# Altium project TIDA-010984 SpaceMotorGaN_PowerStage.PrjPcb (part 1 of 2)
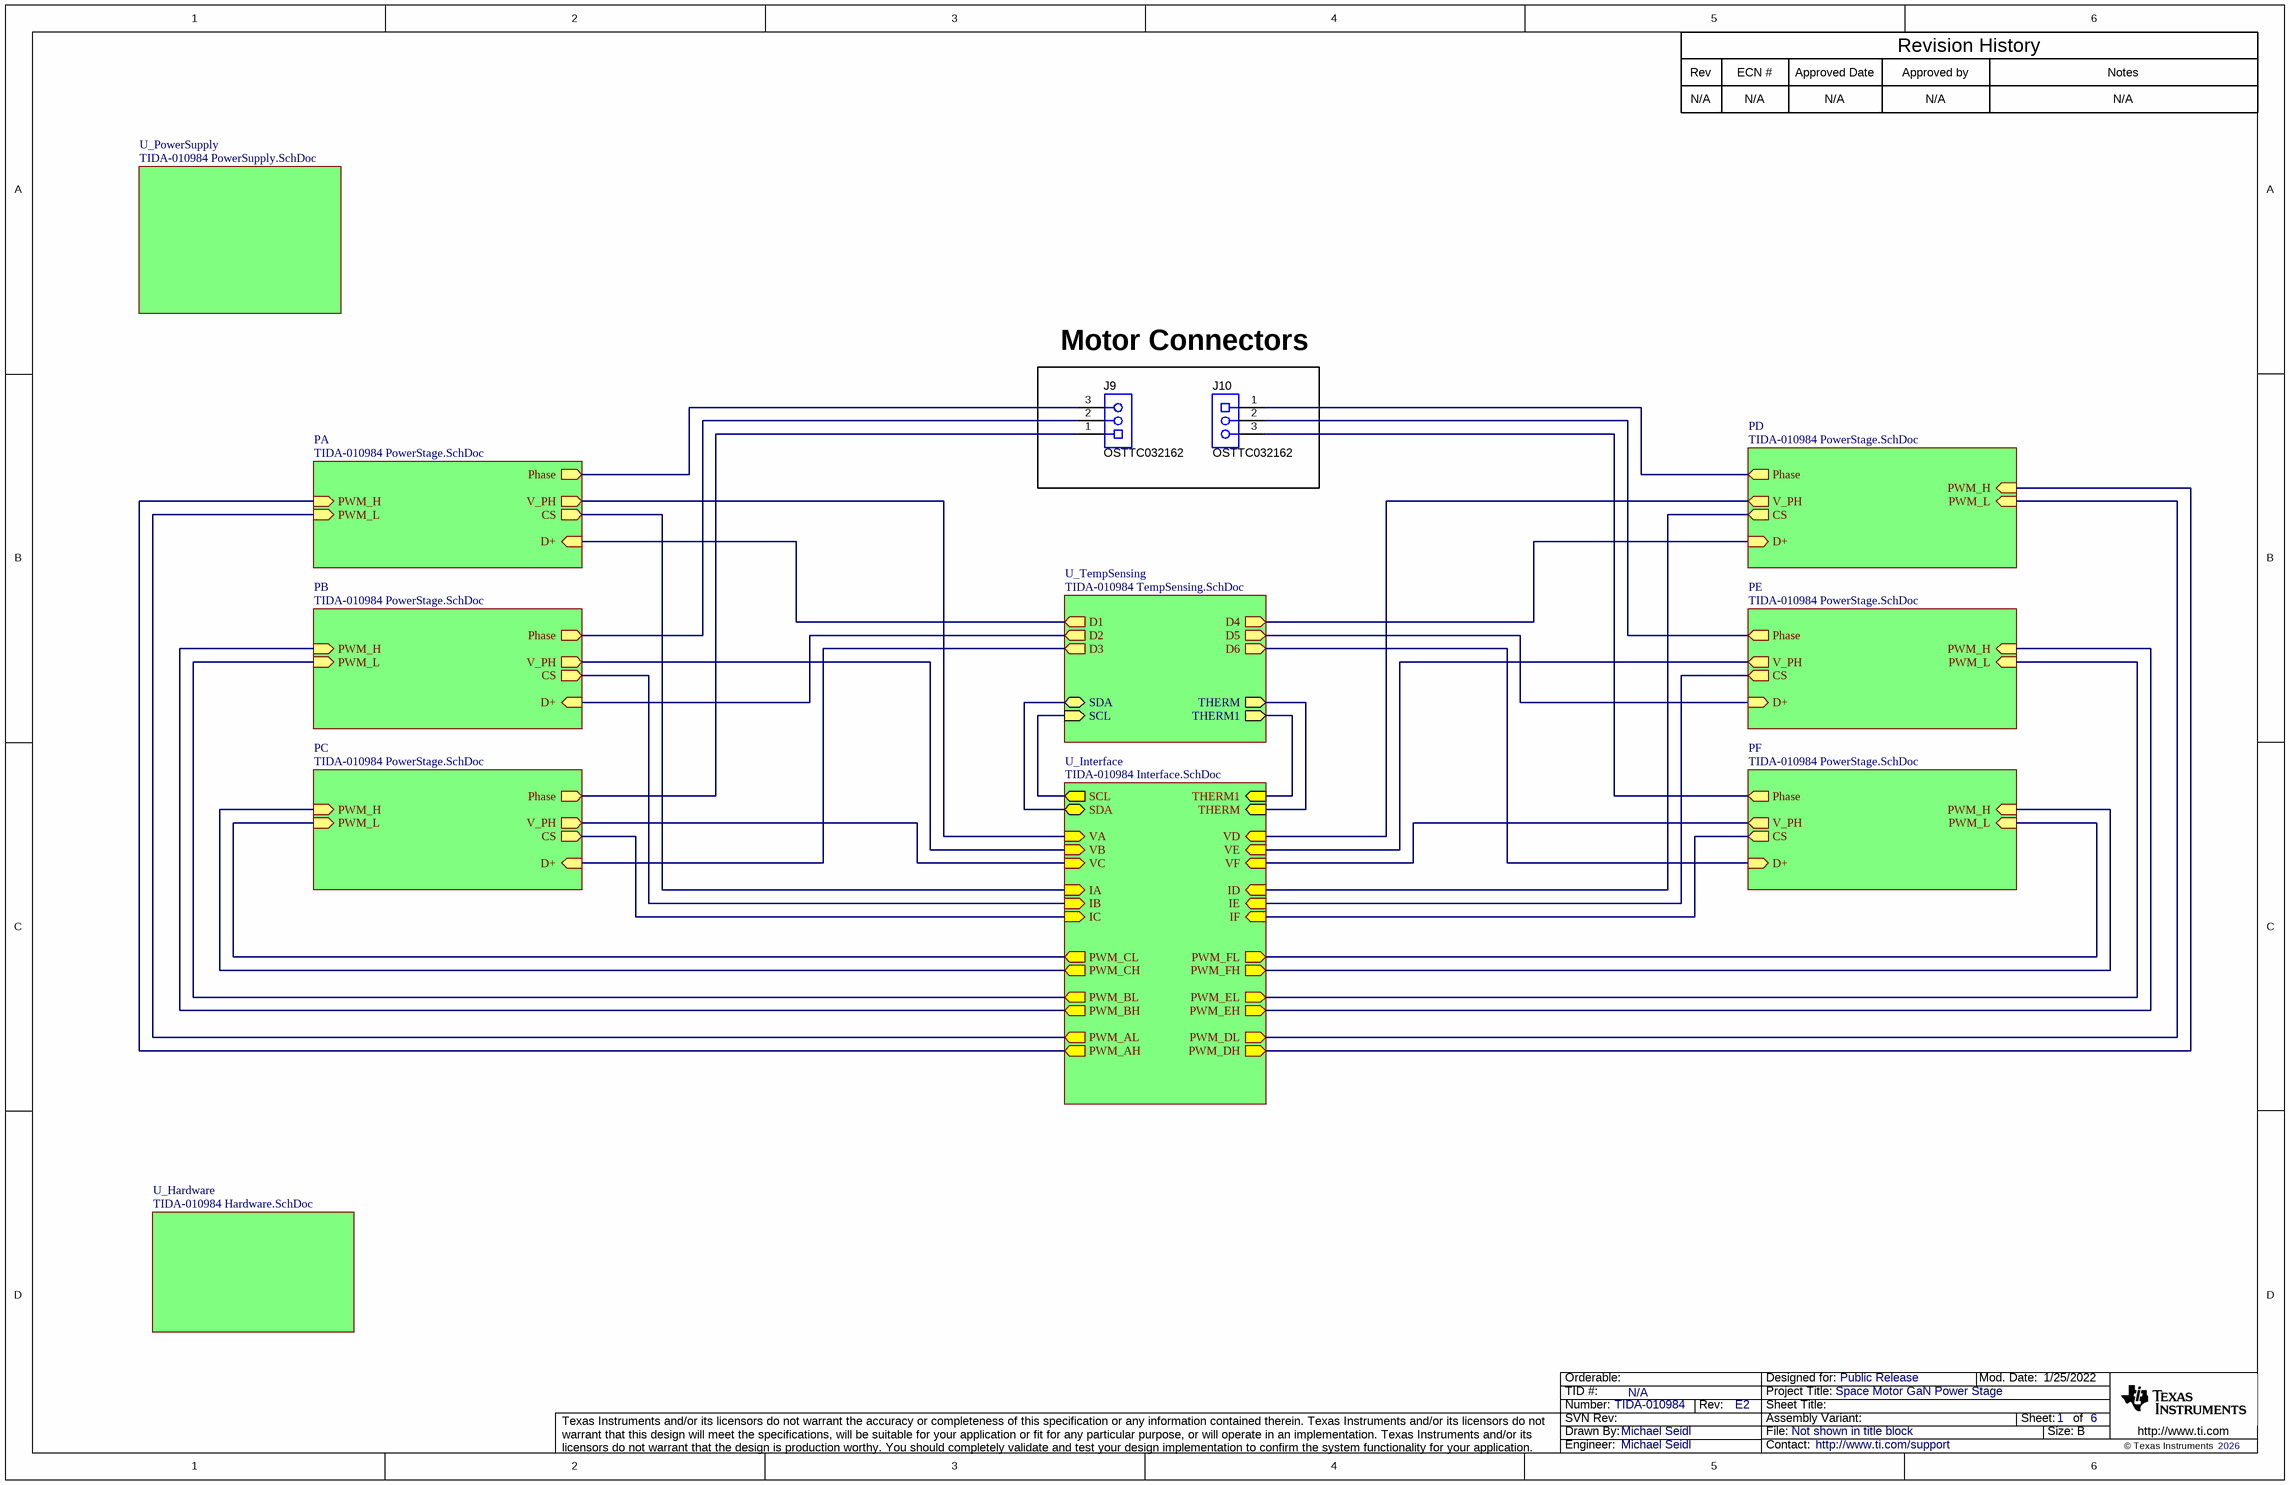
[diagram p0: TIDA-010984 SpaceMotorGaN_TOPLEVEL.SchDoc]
CopyrightYear: 2026; PCB_Layout: Michael Seidl; PCB_Rev: E2; PRJ_Customer: Public Release; PRJ_Engineer: Michael Seidl; PRJ_Number: TIDA-010984; PRJ_Title: Space Motor GaN Power Stage; SCH_Rev: E2; TechSupport: http://www.ti.com/support; TID: N/A
6 sheets, 583 parts. Net scope: hierarchical (ports join the sheet entries above them; power ports are global).
Board file: TIDA-010984 SpaceMotorGaN_PowerStage.PcbDoc
Sheets:
  TIDA-010984 SpaceMotorGaN_TOPLEVEL.SchDoc
    PA = TIDA-010984 PowerStage.SchDoc
    PB = TIDA-010984 PowerStage.SchDoc
    PC = TIDA-010984 PowerStage.SchDoc
    PE = TIDA-010984 PowerStage.SchDoc
    PD = TIDA-010984 PowerStage.SchDoc
    PF = TIDA-010984 PowerStage.SchDoc
    U_Interface = TIDA-010984 Interface.SchDoc
    U_Hardware = TIDA-010984 Hardware.SchDoc
    U_TempSensing = TIDA-010984 TempSensing.SchDoc
    U_PowerSupply = TIDA-010984 PowerSupply.SchDoc

## Sheet TIDA-010984 SpaceMotorGaN_TOPLEVEL.SchDoc
size 431 x 279 mm; Date: Not shown in title block; ApprovedBy: Not shown in title block; CheckedBy: Not shown in title block; Author: Not shown in title block; CompanyName: Not shown in title block; DrawnBy: Michael Seidl; Engineer: Not shown in title block; Organization: Not shown in title block; Address1: Not shown in title block; Address2: Not shown in title block; Address3: Not shown in title block; Address4: Not shown in title block; DocumentNumber: 1; Revision: Use project parameter SCH_Rev; SheetNumber: 1; SheetTotal: 6; PageSetup: Record=PageOptions¦CenterHorizontal=True¦CenterVertical=True¦PrintScale=1.00¦XCorrection=1.00¦YCorrection=1.00¦PrintKind=0¦BorderSize=5000000¦LeftOffset=0¦BottomOffset=0¦Orientation=2¦PaperLength=1000¦PaperWidth=1000¦Scale=100¦PaperSource=15¦PrintQuality=600¦MediaType=1¦DitherType=10¦PaperKind=Letter¦PrintScaleMode=1

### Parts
J9  OSTTC032162  [On-Shore_OSTTC032162]
J10  OSTTC032162  [On-Shore_OSTTC032162]

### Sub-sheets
PA = TIDA-010984 PowerStage.SchDoc: Phase (out), V_PH (out), PWM_H (in), PWM_L (in), CS (out), D+ (in)
PB = TIDA-010984 PowerStage.SchDoc: Phase (out), V_PH (out), PWM_H (in), PWM_L (in), CS (out), D+ (in)
PC = TIDA-010984 PowerStage.SchDoc: Phase (out), V_PH (out), PWM_H (in), PWM_L (in), CS (out), D+ (in)
PD = TIDA-010984 PowerStage.SchDoc: Phase (out), V_PH (out), CS (out), PWM_H (in), PWM_L (in), D+ (in)
PE = TIDA-010984 PowerStage.SchDoc: Phase (out), V_PH (out), CS (out), PWM_H (in), PWM_L (in), D+ (in)
PF = TIDA-010984 PowerStage.SchDoc: Phase (out), V_PH (out), CS (out), PWM_H (in), PWM_L (in), D+ (in)
U_Hardware = TIDA-010984 Hardware.SchDoc: no entries
U_Interface = TIDA-010984 Interface.SchDoc: SDA (bidir), SCL (out), THERM (in), THERM1 (in), PWM_AH (out), PWM_AL (out), PWM_BH (out), PWM_BL (out), PWM_CH (out), PWM_CL (out), PWM_DH (out), PWM_DL (out), PWM_EH (out), PWM_EL (out), PWM_FH (out), PWM_FL (out), VA (in), VB (in), VC (in), IA (in), IB (in), IC (in), VD (in), VE (in), VF (in), ID (in), IE (in), IF (in)
U_PowerSupply = TIDA-010984 PowerSupply.SchDoc: no entries
U_TempSensing = TIDA-010984 TempSensing.SchDoc: THERM (out), THERM1 (out), SDA (bidir), SCL (in), D1 (out), D2 (out), D3 (out), D4 (out), D5 (out), D6 (out)

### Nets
CS: sheet PA/CS, sheet U_Interface/IA
CS: sheet PB/CS, sheet U_Interface/IB  [a separate net that carries the same name]
CS: sheet PC/CS, sheet U_Interface/IC  [a separate net that carries the same name]
CS: sheet PE/CS, sheet U_Interface/IE  [a separate net that carries the same name]
CS: sheet PD/CS, sheet U_Interface/ID  [a separate net that carries the same name]
CS: sheet PF/CS, sheet U_Interface/IF  [a separate net that carries the same name]
D+: sheet PA/D+, sheet U_TempSensing/D1
D+: sheet PB/D+, sheet U_TempSensing/D2  [a separate net that carries the same name]
D+: sheet PC/D+, sheet U_TempSensing/D3  [a separate net that carries the same name]
D+: sheet PE/D+, sheet U_TempSensing/D5  [a separate net that carries the same name]
D+: sheet PD/D+, sheet U_TempSensing/D4  [a separate net that carries the same name]
D+: sheet PF/D+, sheet U_TempSensing/D6  [a separate net that carries the same name]
Phase: J10.1 ; sheet PD/Phase
Phase: J10.2 ; sheet PE/Phase  [a separate net that carries the same name]
Phase: J10.3 ; sheet PF/Phase  [a separate net that carries the same name]
Phase: J9.1 ; sheet PC/Phase  [a separate net that carries the same name]
Phase: J9.2 ; sheet PB/Phase  [a separate net that carries the same name]
Phase: J9.3 ; sheet PA/Phase  [a separate net that carries the same name]
PWM_AH: sheet PA/PWM_H, sheet U_Interface/PWM_AH
PWM_AL: sheet PA/PWM_L, sheet U_Interface/PWM_AL
PWM_BH: sheet PB/PWM_H, sheet U_Interface/PWM_BH
PWM_BL: sheet PB/PWM_L, sheet U_Interface/PWM_BL
PWM_CH: sheet PC/PWM_H, sheet U_Interface/PWM_CH
PWM_CL: sheet PC/PWM_L, sheet U_Interface/PWM_CL
PWM_DH: sheet PD/PWM_H, sheet U_Interface/PWM_DH
PWM_DL: sheet PD/PWM_L, sheet U_Interface/PWM_DL
PWM_EH: sheet PE/PWM_H, sheet U_Interface/PWM_EH
PWM_EL: sheet PE/PWM_L, sheet U_Interface/PWM_EL
PWM_FH: sheet PF/PWM_H, sheet U_Interface/PWM_FH
PWM_FL: sheet PF/PWM_L, sheet U_Interface/PWM_FL
SCL: sheet U_Interface/SCL, sheet U_TempSensing/SCL
SDA: sheet U_Interface/SDA, sheet U_TempSensing/SDA
THERM: sheet U_Interface/THERM, sheet U_TempSensing/THERM
THERM1: sheet U_Interface/THERM1, sheet U_TempSensing/THERM1
V_PH: sheet PA/V_PH, sheet U_Interface/VA
V_PH: sheet PB/V_PH, sheet U_Interface/VB  [a separate net that carries the same name]
V_PH: sheet PC/V_PH, sheet U_Interface/VC  [a separate net that carries the same name]
V_PH: sheet PE/V_PH, sheet U_Interface/VE  [a separate net that carries the same name]
V_PH: sheet PD/V_PH, sheet U_Interface/VD  [a separate net that carries the same name]
V_PH: sheet PF/V_PH, sheet U_Interface/VF  [a separate net that carries the same name]

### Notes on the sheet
- Rev
- N/A
- ECN #
- Approved Date
- Approved by
- Revision History
- Notes
- Motor Connectors

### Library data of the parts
J9 J10 = CMP-0075292-1: Terminal Block, 3x1, 5.08 mm, Tin, TH; Manufacturer: On-Shore Technology; Pitch_mm: 5.08; Gender: Female; Row_Count: 1; Current_A: 15A; Voltage_V: 300V; Cert_UL: Y; CNHeader: False; CT: True

## Sheet TIDA-010984 PowerStage.SchDoc
size 431 x 279 mm; Date: Not shown in title block; ApprovedBy: Not shown in title block; CheckedBy: Not shown in title block; Author: Not shown in title block; CompanyName: Not shown in title block; DrawnBy: Michael Seidl; Engineer: Not shown in title block; Organization: Not shown in title block; Address1: Not shown in title block; Address2: Not shown in title block; Address3: Not shown in title block; Address4: Not shown in title block; DocumentNumber: 2; Revision: Use project parameter SCH_Rev; SheetNumber: 4; SheetTotal: 6; PageSetup: Record=PageOptions¦CenterHorizontal=True¦CenterVertical=True¦PrintScale=1.00¦XCorrection=1.00¦YCorrection=1.00¦PrintKind=0¦BorderSize=5000000¦LeftOffset=0¦BottomOffset=0¦Orientation=2¦PaperLength=1000¦PaperWidth=1000¦Scale=100¦PaperSource=15¦PrintQuality=600¦MediaType=1¦DitherType=10¦PaperKind=Letter¦PrintScaleMode=1
Used 6 times, as channels PA, PB, PC, PE, PD, PF. Parts and nets are listed once, with the designators drawn on the sheet.
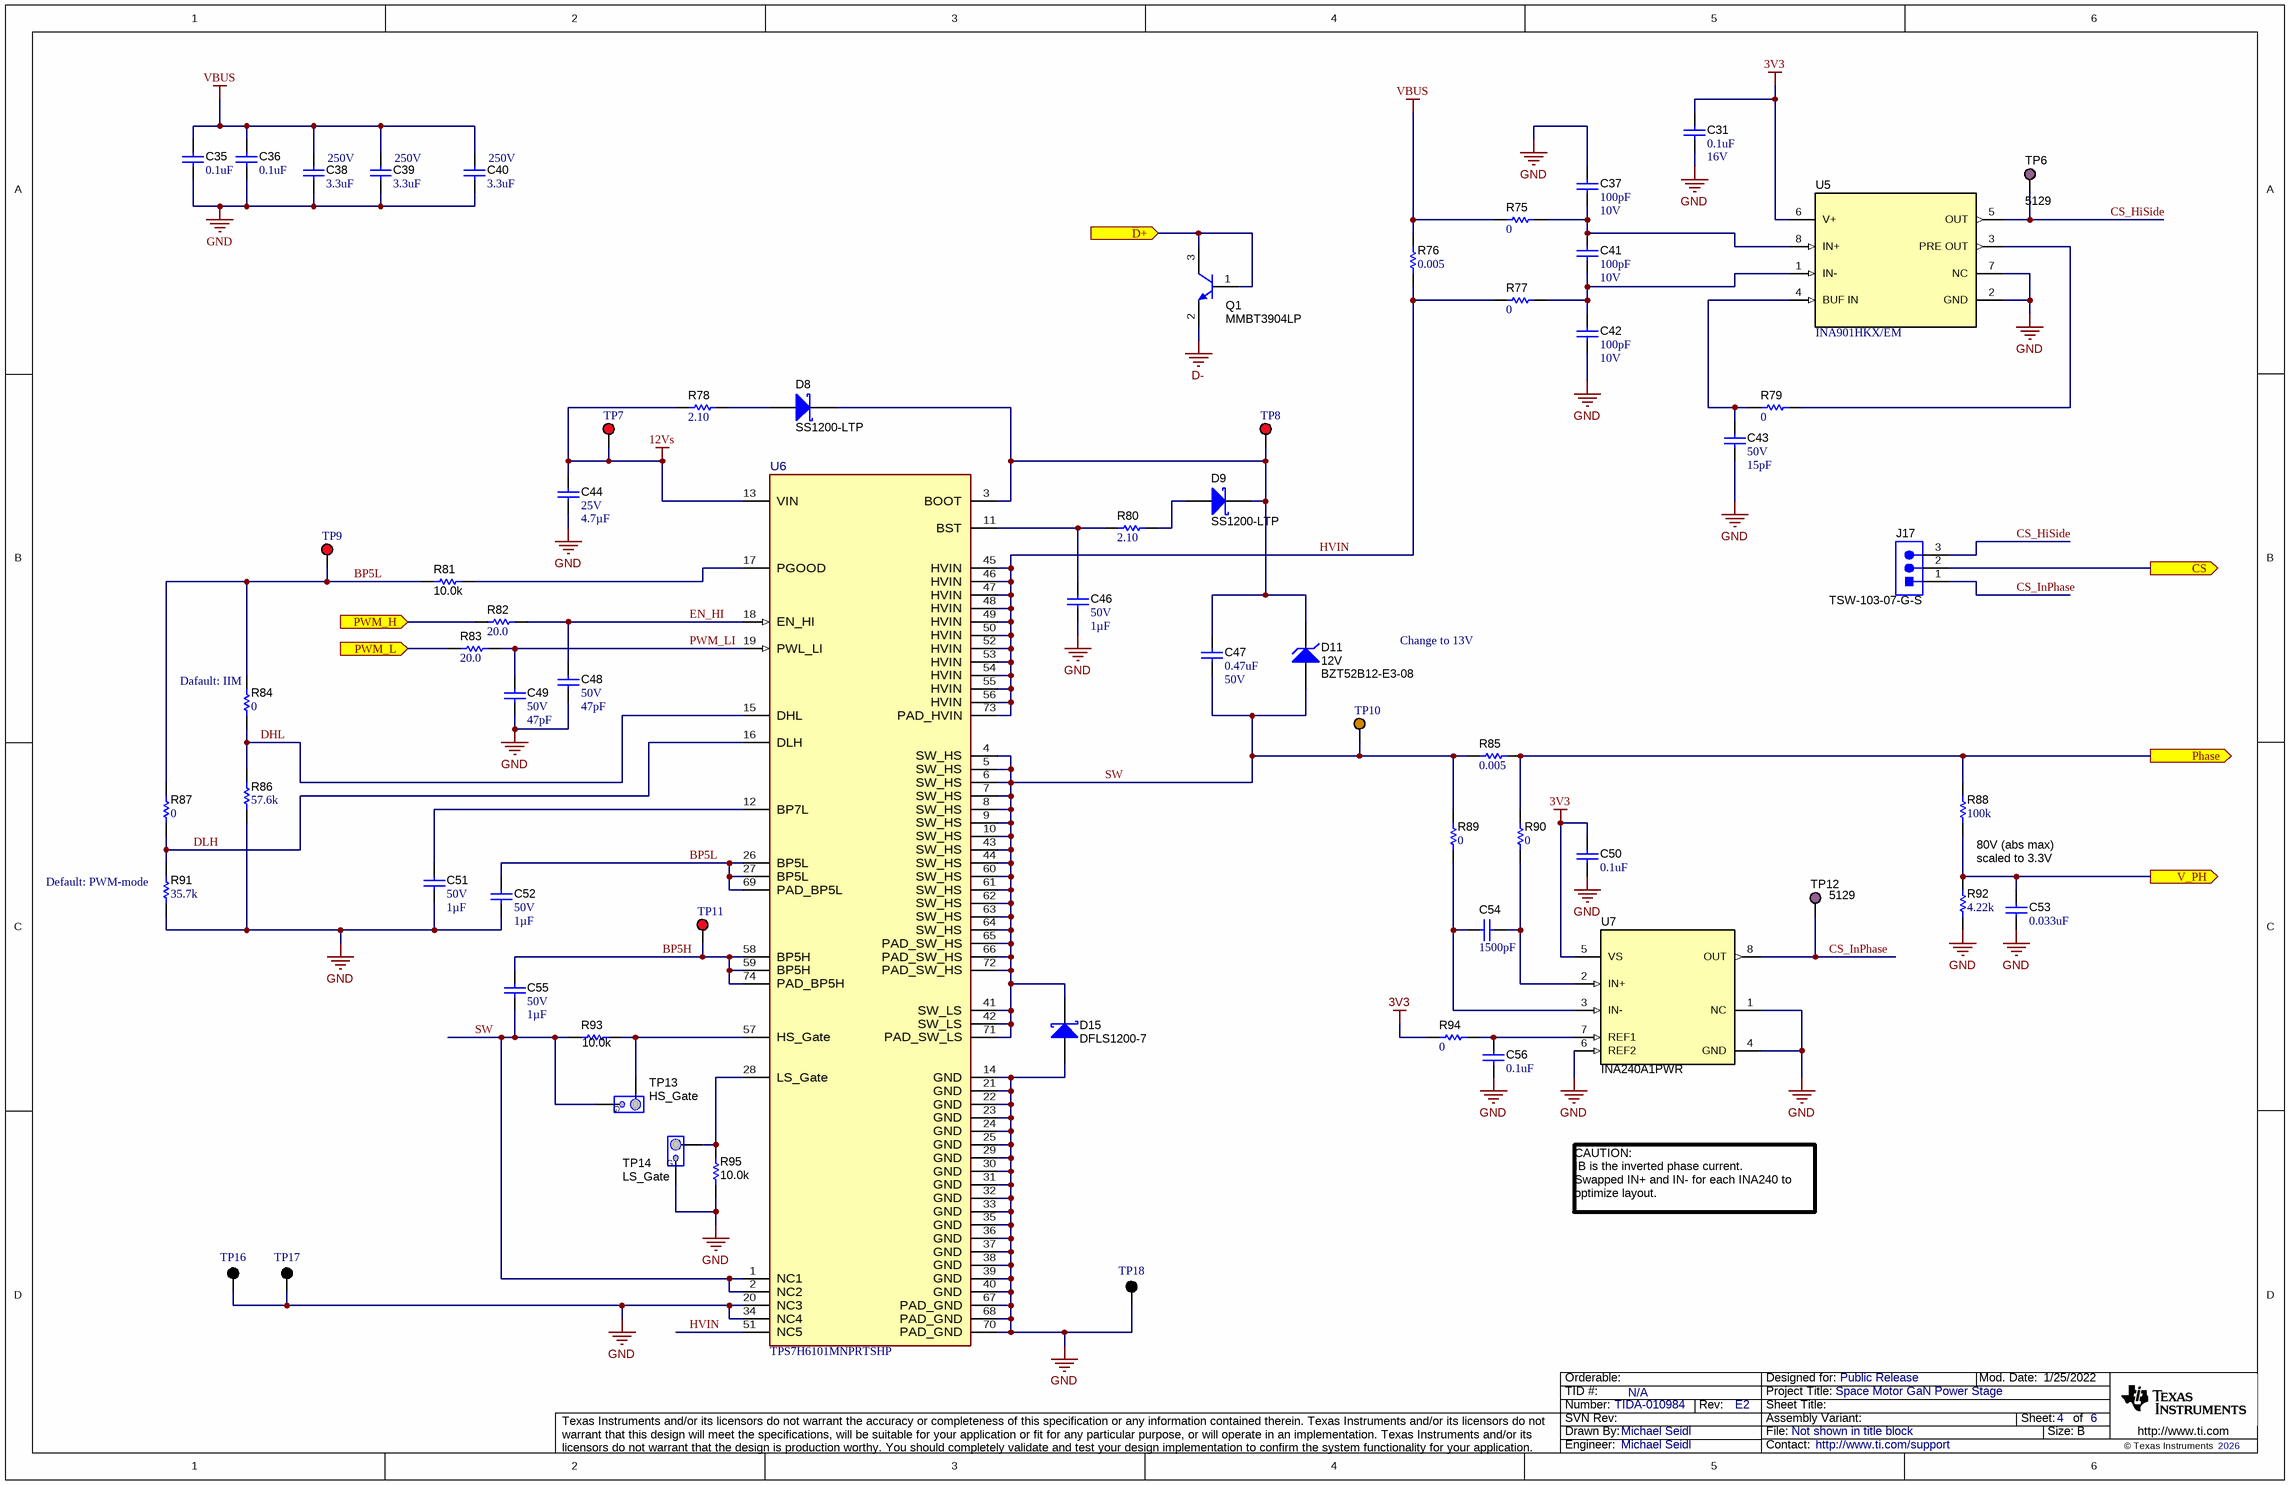
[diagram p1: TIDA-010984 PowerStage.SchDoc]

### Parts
C31  ValueDisplayed: 0.1uF  VDC_V: 16V  [0603]  (hidden comment: GRM188R71C104KA01D)
C35  ValueDisplayed: 0.1uF  [1206_180]  (hidden comment: GRM31CR72E104KW03L)
C36  ValueDisplayed: 0.1uF  [1206_180]  (hidden comment: GRM31CR72E104KW03L)
C37  Cap_F: 100pF  VDC_V: 10V  [0603]  (hidden comment: 0603ZC101KAT2A)
C38  ValueDisplayed: 3.3uF  Value2: 250V  [CKG57N]  (hidden comment: CKG57NX7T2E335M500JH)
C39  ValueDisplayed: 3.3uF  Value2: 250V  [CKG57N]  (hidden comment: CKG57NX7T2E335M500JH)
C40  ValueDisplayed: 3.3uF  Value2: 250V  [CKG57N]  (hidden comment: CKG57NX7T2E335M500JH)
C41  Cap_F: 100pF  VDC_V: 10V  [0603]  (hidden comment: 0603ZC101KAT2A)
C42  Cap_F: 100pF  VDC_V: 10V  [0603]  (hidden comment: 0603ZC101KAT2A)
C43  VDC_V: 50V  ValueDisplayed: 15pF  [0603]  (hidden comment: GCM1885C1H150JA16D)
C44  VDC_V: 25V  ValueDisplayed: 4.7µF  [0805L]  (hidden comment: CGA4J1X7R1E475K125AC)
C46  VDC_V: 50V  ValueDisplayed: 1µF  [0805_HV]  (hidden comment: 08055C105K4Z2A)
C47  ValueDisplayed: 0.47uF  VDC_V: 50V  [0603]  (hidden comment: CGA3E3X7R1H474K080AE)
C48  VDC_V: 50V  ValueDisplayed: 47pF  [0603]  (hidden comment: CGA3E2NP01H470J080AA)
C49  VDC_V: 50V  ValueDisplayed: 47pF  [0603]  (hidden comment: CGA3E2NP01H470J080AA)
C50  ValueDisplayed: 0.1uF  [0603]  (hidden comment: GRM188R71C104KA01D)
C51  VDC_V: 50V  ValueDisplayed: 1µF  [0805_HV]  (hidden comment: 08055C105K4Z2A)
C52  VDC_V: 50V  ValueDisplayed: 1µF  [0805_HV]  (hidden comment: 08055C105K4Z2A)
C53  ValueDisplayed: 0.033uF  [0603]  (hidden comment: GRM188R71C333KA01D)
C54  ValueDisplayed: 1500pF  [0603]  (hidden comment: GRM1885C1E152JA01D)
C55  VDC_V: 50V  ValueDisplayed: 1µF  [0805_HV]  (hidden comment: 08055C105K4Z2A)
C56  ValueDisplayed: 0.1uF  [0603]  (hidden comment: GRM188R71C104KA01D)
D8  SS1200-LTP  [SMA]
D9  SS1200-LTP  [SMA]
D11  BZT52B12-E3-08  value 12V  [SOD-123]
D15  DFLS1200-7  [PowerDI123]
J17  TSW-103-07-G-S  [TSW-103-07-G-S]
Q1  MMBT3904LP  [DIODES_X1-DFN1006-3]
R75  ValueDisplayed: 0  [0603]  (hidden comment: RC0603JR-070RL)
R76  ValueDisplayed: 0.005  [CRE2512-R5_R9]  (hidden comment: CRE2512-FZ-R005E-3)
R77  ValueDisplayed: 0  [0603]  (hidden comment: RC0603JR-070RL)
R78  ValueDisplayed: 2.10  [0603]  (hidden comment: RC0603FR-072R1L)
R79  ValueDisplayed: 0  [0603]  (hidden comment: RC0603JR-070RL)
R80  ValueDisplayed: 2.10  [0603]  (hidden comment: RC0603FR-072R1L)
R81  ValueDisplayed: 10.0k  [0603]  (hidden comment: RC0603FR-0710KL)
R82  ValueDisplayed: 20.0  [0603]  (hidden comment: CRCW060320R0FKEA)
R83  ValueDisplayed: 20.0  [0603]  (hidden comment: CRCW060320R0FKEA)
R84  ValueDisplayed: 0  [0603]  (hidden comment: RC0603JR-070RL)
R85  ValueDisplayed: 0.005  [CRE2512-R5_R9]  (hidden comment: CRE2512-FZ-R005E-3)
R86  ValueDisplayed: 57.6k  [0603]  (hidden comment: RC0603FR-0757K6L)
R87  ValueDisplayed: 0  [0603]  (hidden comment: RC0603JR-070RL)
R88  ValueDisplayed: 100k  [0603]  (hidden comment: RC0603FR-07100KL)
R89  ValueDisplayed: 0  [0603]  (hidden comment: RC0603JR-070RL)
R90  ValueDisplayed: 0  [0603]  (hidden comment: RC0603JR-070RL)
R91  ValueDisplayed: 35.7k  [0603]  (hidden comment: RC0603FR-0735K7L)
R92  ValueDisplayed: 4.22k  [0603]  (hidden comment: RC0603FR-074K22L)
R93  ValueDisplayed: 10.0k  [0603]  (hidden comment: RC0603FR-0710KL)
R94  ValueDisplayed: 0  [0603]  (hidden comment: RC0603JR-070RL)
R95  ValueDisplayed: 10.0k  [0603]  (hidden comment: RC0603FR-0710KL)
TP6  5129  [Keystone5129]
TP7  5010  [Keystone5010]  (value not drawn)
TP8  5010  [Keystone5010]  (value not drawn)
TP9  5010  [Keystone5010]  (value not drawn)
TP10  5013  [Keystone5013]  (value not drawn)
TP11  5010  [Keystone5010]  (value not drawn)
TP12  5129  [Keystone5129]
TP13  HS_Gate  [TESTPOINT_PIGTAIL]  (no BOM)
TP14  LS_Gate  [TESTPOINT_PIGTAIL]  (no BOM)
TP16  5011  [Keystone5011]  (value not drawn)
TP17  5011  [Keystone5011]  (value not drawn)
TP18  5011  [Keystone5011]  (value not drawn)
U5  INA901HKX/EM  [HKX0008A_Custom_A]
U6  TPS7H6101MNPRTSHP  [NPR0064A-MFG]
U7  INA240A1PWR  [PW0008A_L]

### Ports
CS (out), D+ (in), Phase (out), PWM_H (in), PWM_L (in), V_PH (out)

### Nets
3V3: C31.1 C50.2 R94.1 U5.6(V+) U7.5(VS)
12Vs: C44.2 R78.2 TP7.1 U6.13(VIN)
D-: Q1.2(E)
GND: C31.2 C35.2 C36.2 C37.1 C38.2 C39.2 C40.2 C42.2 C43.2 C44.1 C46.1 C48.2 C49.2 C50.1 C51.1 C52.1 C53.2 C56.1 D15.2(A) R86.2 R91.2 R92.1 R95.1 TP14.2 TP16.1 TP17.1 TP18.1 U5.2(GND) U5.7(NC) U6.14(GND) U6.20(NC3) U6.21(GND) U6.22(GND) U6.23(GND) U6.24(GND) U6.25(GND) U6.29(GND) U6.30(GND) U6.31(GND) U6.32(GND) U6.33(GND) U6.34(NC4) U6.35(GND) U6.36(GND) U6.37(GND) U6.38(GND) U6.39(GND) U6.40(GND) U6.67(PAD_GND) U6.68(PAD_GND) U6.70(PAD_GND) U7.1(NC) U7.4(GND) U7.6(REF2)
VBUS: C35.1 C36.1 C38.1 C39.1 C40.1 R75.1 R76.2
BP5H: C55.2 TP11.1 U6.58(BP5H) U6.59(BP5H) U6.74(PAD_BP5H)
BP5L: C52.2 R81.2 R84.1 R87.1 TP9.1 U6.26(BP5L) U6.27(BP5L) U6.69(PAD_BP5L)
CS: J17.2 ; port CS
CS_HiSide: J17.3 TP6.1 U5.5(OUT)
CS_InPhase: J17.1 TP12.1 U7.8(OUT)
D+: Q1.1(B) Q1.3(C) ; port D+
DHL: R84.2 R86.1 U6.15(DHL)
DLH: R87.2 R91.1 U6.16(DLH)
EN_HI: C48.1 R82.1 U6.18(EN_HI)
HVIN: R76.1 R77.1 U6.45(HVIN) U6.46(HVIN) U6.47(HVIN) U6.48(HVIN) U6.49(HVIN) U6.50(HVIN) U6.51(NC5) U6.52(HVIN) U6.53(HVIN) U6.54(HVIN) U6.55(HVIN) U6.56(HVIN) U6.73(PAD_HVIN)
Phase: R85.2 R88.2 R90.1 ; port Phase
PWM_H: R82.2 ; port PWM_H
PWM_L: R83.2 ; port PWM_L
PWM_LI: C49.1 R83.1 U6.19(PWL_LI)
SW: C47.2 C55.1 D11.2(A) D15.1(K) R85.1 R89.1 R93.2 TP10.1 TP13.2 U6.1(NC1) U6.2(NC2) U6.4(SW_HS) U6.5(SW_HS) U6.6(SW_HS) U6.7(SW_HS) U6.8(SW_HS) U6.9(SW_HS) U6.10(SW_HS) U6.41(SW_LS) U6.42(SW_LS) U6.43(SW_HS) U6.44(SW_HS) U6.60(SW_HS) U6.61(SW_HS) U6.62(SW_HS) U6.63(SW_HS) U6.64(SW_HS) U6.65(PAD_SW_HS) U6.66(PAD_SW_HS) U6.71(PAD_SW_LS) U6.72(PAD_SW_HS)
V_PH: C53.1 R88.1 R92.2 ; port V_PH
NetC37_2: C37.2 C41.1 R75.2 U5.8(IN+)
NetC41_2: C41.2 C42.1 R77.2 U5.1(IN-)
NetC43_1: C43.1 R79.1 U5.4(BUF_IN)
NetC46_2: C46.2 R80.2 U6.11(BST)
NetC47_1: C47.1 D8.1(K) D9.1(K) D11.1(K) TP8.1 U6.3(BOOT)
NetC51_2: C51.2 U6.12(BP7L)
NetC54_1: C54.1 R89.2 U7.3(IN-)
NetC54_2: C54.2 R90.2 U7.2(IN+)
NetC56_2: C56.2 R94.2 U7.7(REF1)
NetD8_2: D8.2(A) R78.1
NetD9_2: D9.2(A) R80.1
NetR79_2: R79.2 U5.3(PRE_OUT)
NetR81_1: R81.1 U6.17(PGOOD)
NetR93_1: R93.1 TP13.1 U6.57(HS_Gate)
NetR95_2: R95.2 TP14.1 U6.28(LS_Gate)

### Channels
PA: designators end in _PA; ports CS=CS D+=D+ Phase=Phase PWM_H=PWM_AH PWM_L=PWM_AL V_PH=V_PH
PB: designators end in _PB; ports CS=CS D+=D+ Phase=Phase PWM_H=PWM_BH PWM_L=PWM_BL V_PH=V_PH
PC: designators end in _PC; ports CS=CS D+=D+ Phase=Phase PWM_H=PWM_CH PWM_L=PWM_CL V_PH=V_PH
PE: designators end in _PE; ports CS=CS D+=D+ Phase=Phase PWM_H=PWM_EH PWM_L=PWM_EL V_PH=V_PH
PD: designators end in _PD; ports CS=CS D+=D+ Phase=Phase PWM_H=PWM_DH PWM_L=PWM_DL V_PH=V_PH
PF: designators end in _PF; ports CS=CS D+=D+ Phase=Phase PWM_H=PWM_FH PWM_L=PWM_FL V_PH=V_PH

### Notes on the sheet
- (near R84) Dafault: IIM
- Change to 13V
- (near R91) Default: PWM-mode
- 80V (abs max) scaled to 3.3V
- CAUTION:
  IB is the inverted phase current.
  Swapped IN+ and IN- for each INA240 to optimize layout.

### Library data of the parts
C31 = CMP-0007378-5: CAP, CERM, 0.1 uF, 16 V, +/- 10%, X7R, 0603; Manufacturer: MuRata; SizeArea_mm2: 1.28; SizeX_mm: 1.6; U/M: EA; Value: 0.1uF; TaMin_C: -55°C; Polarized: N; SizeZ_mm: 1; Value1: Unknown; SizeY_mm: 0.8; Cap_F: 100nF; TaMax_C: 125°C; SizeAreaWB_mm2: 4.68; AEC Category: Q200
C35 C36 = CMP-0008973-2: CAP, CERM, 0.1 uF, 250 V, +/- 10%, X7R, 1206; Manufacturer: MuRata; TaMin_C: -55°C; Polarized: N; SizeAreaWB_mm2: 10.92; Value1: Unknown; U/M: EA; Value: 0.1uF; TaMax_C: 125°C; SizeZ_mm: 1.8; SizeX_mm: 3.2; SizeY_mm: 1.6; Cap_Case: 1206; Value2: 250V; SizeArea_mm2: 5.12; CompType: Capacitor; Cap_F: 100nF; AEC Category: Q200
C37 C41 C42 = CMP-0006812-4: CAP, CERM, 100 pF, 10 V, +/- 10%, X7R, 0603; Manufacturer: AVX; TaMin_C: -55°C; Polarized: N; SizeAreaWB_mm2: 4.68; Value1: Unknown; U/M: EA; Value: 100pF; TaMax_C: 125°C; SizeZ_mm: 1; SizeX_mm: 1.6; SizeY_mm: 0.8; SizeArea_mm2: 1.28; AEC Category: Q200
C38-C40 = CMP-0009427-2: CAP, CERM, 3.3 uF, 250 V, +/- 20%, X7T, AEC-Q200 Grade 1, 6x5x5mm; Manufacturer: TDK; Polarized: N; Value: 3.3uF; U/M: EA; Cap_F: 3.3µF; Value1: Unknown; TaMin_C: -55°C; TaMax_C: 125°C; Cap_Case: 2220; AEC Category: Q200; AEC Qualified: Y; AEC Grade: 1; SizeAreaWB_mm2: 56; SizeZ_mm: 5.5; SizeX_mm: 6; SizeY_mm: 5; SizeArea_mm2: 30
C43 = CMP-0007126-4: CAP, CERM, 15 pF, 50 V, +/- 5%, C0G/NP0, AEC-Q200 Grade 1, 0603; Manufacturer: MuRata; TaMin_C: -55°C; Polarized: N; SizeAreaWB_mm2: 4.68; Value1: Unknown; U/M: EA; Value: 15pF; TaMax_C: 125°C; SizeZ_mm: 1; SizeX_mm: 1.6; SizeY_mm: 0.8; SizeArea_mm2: 1.28; AEC Qualified: Y; AEC Category: Q200
C44 = CMP-0076706-1: CAP, CERM, 4.7 µF, 25 V,+/- 10%, X7R, AEC-Q200 Grade 1, 0805; Manufacturer: TDK; TaMin_C: -55°C; Polarized: N; SizeAreaWB_mm2: 6.75; U/M: EA; Value: 4.7uF; TaMax_C: 125°C; SizeZ_mm: 1.45; SizeX_mm: 2.0; SizeY_mm: 1.25; Cap_Case: 2x1.25x1.25mm; SizeArea_mm2: 2.5; AEC Qualified: Y; AEC Grade: 1; AEC Category: Q200
C46 C51 C52 C55 = CMP-0083705-1: CAP, CERM, 1 µF, 50 V,+/- 10%, X7R, AEC-Q200 Grade 1, 0805; Manufacturer: AVX; TaMin_C: -55°C; Polarized: N; SizeAreaWB_mm2: 6.75; U/M: EA; Value: 1uF; TaMax_C: 125°C; SizeZ_mm: 1.45; SizeX_mm: 2; SizeY_mm: 1.25; Cap_Case: 0805; SizeArea_mm2: 2.5; AEC Qualified: Y; AEC Grade: 1; AEC Category: Q200
C47 = CMP-0007097-4: CAP, CERM, 0.47 uF, 50 V, +/- 10%, X7R, AEC-Q200 Grade 1, 0603; Manufacturer: TDK; SizeArea_mm2: 1.28; AEC Qualified: Y; SizeX_mm: 1.6; U/M: EA; Value: 0.47uF; TaMin_C: -55°C; Polarized: N; AEC Grade: 1; Value1: Unknown; SizeY_mm: 0.8; Cap_F: 470nF; TaMax_C: 125°C; SizeAreaWB_mm2: 4.68; AEC Category: Q200
C48 C49 = CMP-0080062-1: CAP, CERM, 47 pF, 50 V,+/- 5%, C0G/NP0, AEC-Q200 Grade 0, 0603; Manufacturer: TDK; TaMin_C: -55°C; Polarized: N; SizeAreaWB_mm2: 4.68; U/M: EA; Value: 47pF; TaMax_C: 150°C; SizeZ_mm: 1; SizeX_mm: 1.6; SizeY_mm: 0.8; SizeArea_mm2: 1.28; AEC Qualified: Y; AEC Grade: 0; AEC Category: Q200
C50 C56 = CMP-0007378-5: CAP, CERM, 0.1 uF, 16 V, +/- 10%, X7R, 0603; Manufacturer: MuRata; Polarized: N; Value: 0.1uF; U/M: EA; Cap_F: 100nF; Value1: Unknown; VDC_V: 16V; TaMin_C: -55°C; TaMax_C: 125°C; AEC Category: Q200; SizeArea_mm2: 1.28; SizeAreaWB_mm2: 4.68; SizeX_mm: 1.6; SizeY_mm: 0.8; SizeZ_mm: 1
C53 = CMP-0007392-5: CAP, CERM, 0.033 uF, 16 V, +/- 10%, X7R, 0603; Manufacturer: MuRata; Polarized: N; U/M: EA; Cap_F: 33nF; Value1: Unknown; VDC_V: 16V; TaMin_C: -55°C; TaMax_C: 125°C; AEC Category: Q200; SizeArea_mm2: 1.28; SizeAreaWB_mm2: 4.68; SizeX_mm: 1.6; SizeY_mm: 0.8; SizeZ_mm: 1
C54 = CMP-0007163-4: CAP, CERM, 1500 pF, 25 V, +/- 5%, C0G/NP0, 0603; Manufacturer: MuRata; TaMin_C: -55°C; Polarized: N; SizeAreaWB_mm2: 4.68; Value1: Unknown; U/M: EA; Value: 1500pF; TaMax_C: 125°C; SizeZ_mm: 1; SizeX_mm: 1.6; SizeY_mm: 0.8; Value2: 25V; SizeArea_mm2: 1.28; Cap_F: 1.5nF; AEC Category: Q200
D8 D9 = CMP-0028981-2: Diode, Schottky, 200 V, 1 A, SMA; Manufacturer: Micro Commercial Components; TJmax_C: 150°C; SizeArea_mm2: 16.3228; Io_A: 1A; AEC Qualified: N; SizeX_mm: 5.59; SizeZ_mm: 2.87; Vf_V: 920mV; Value: 200V; AEC Category: Q101; Value2: 0.92V; SizeY_mm: 2.92; SizeAreaWB_mm2: 37.3428
D11 = CMP-0005773-4: Diode, Zener, 12 V, 500 mW, AEC-Q101, SOD-123; Manufacturer: Vishay-Semiconductor; SizeX_mm: 3.85; RJA_CperW: 300; SizeY_mm: 1.7; AEC Qualified: Y; SizeZ_mm: 1.35; Power_W: 500mW; AEC Category: Q101; SizeAreaWB_mm2: 13.095; Value1: 0.5W; SizeArea_mm2: 6.545
D15 = CMP-0028517-2: Diode, Schottky, 200 V, 1 A, PowerDI123; Manufacturer: Diodes Inc.; Vr_V: 200V; SizeZ_mm: 0.98; Value: 200V; TJmax_C: 175°C; SizeY_mm: 1.78; Vf_V: 850mV; Green_REACh: Passed; Io_A: 1A; Value2: 0.85V; SizeAreaWB_mm2: 13.066; SizeArea_mm2: 6.586; Green_Lifecycle: Active; AEC Category: Q101; SizeX_mm: 3.7; RJC_CperW: 7
J17 = CMP-0075407-2: Header, 100mil, 3x1, Gold, TH; Manufacturer: Samtec; Pitch_mm: 2.54; Cert_VDE: N; Gender: Male; Cert_CSA: Y; Voltage_V: 550V; Green_REACh: Passed; Current_A: 6.3A; Green_Lifecycle: Active; Row_Count: 1
Q1 = CMP-0000409-2: Transistor, NPN, 40 V, 0.2 A, 3-UFDFN; Manufacturer: Diodes Inc.; CompType: BJT; PNP: 0; NPN: 1; Vceo_V: 40V; Vcesat1_V: 300mV; Value: 40 V; IcRated_A: 200mA; Value1: 0.2 A; HfeMax: 400; TaMin_C: -55°C; TaMax_C: 150°C; U/M: EA; AEC Category: Q101; SizeY_mm: 0.6; SizeZ_mm: 0.53; SizeAreaWB_mm2: 3.2
R75 R77 R79 R84 R87 R89 R90 R94 = CMP-0025885-5: RES, 0, 5%, 0.1 W, 0603; Manufacturer: Yageo; Power_W: 100mW; TempCo: 200 ppm/C; Value_Code: 0000; Value: 0; EIA_Code: E24; SizeX_mm: 1.6; SizeY_mm: 0.8; SizeZ_mm: 1; Value2: 0.1W; SizeArea_mm2: 1.28; AEC Qualified: N; VDC_V: 75V; AEC Category: Q200; SizeAreaWB_mm2: 4.68
R76 R85 = CMP-0015751-2: RES, 0.005, 1%, 3 W, AEC-Q200 Grade 0, 2512; Manufacturer: Bourns; Value: 0.005; Res_ohm: 5m; Value_Code: 5L000; Power_W: 3W; TempCo: 75 ppm/C; EIA_Code: E96; U/M: EA; AEC Category: Q200; AEC Qualified: Y; AEC Grade: 0; SizeArea_mm2: 21.6075; SizeX_mm: 6.45; SizeY_mm: 3.35; SizeZ_mm: 0.9
R78 R80 = CMP-0023006-4: RES, 2.10, 1%, 0.1 W, 0603; Manufacturer: Yageo; Power_W: 100mW; TempCo: 200 ppm/C; Value_Code: 2R10; Value: 2.10; EIA_Code: E96; Res_ohm: 2.1; SizeX_mm: 1.6; SizeY_mm: 0.8; SizeZ_mm: 1; Value2: 0.1W; SizeArea_mm2: 1.28; AEC Qualified: N; VDC_V: 75V; AEC Category: Q200; SizeAreaWB_mm2: 4.68
R81 R93 R95 = CMP-0022746-5: RES, 10.0 k, 1%, 0.1 W, 0603; Manufacturer: Yageo; Power_W: 100mW; TempCo: 100 ppm/C; Value_Code: 10k0; Value: 10.0k; EIA_Code: E96; Res_ohm: 10k; SizeX_mm: 1.6; SizeY_mm: 0.8; SizeZ_mm: 1; Value2: 0.1W; SizeArea_mm2: 1.28; AEC Qualified: N; VDC_V: 75V; AEC Category: Q200; SizeAreaWB_mm2: 4.68
R82 R83 = CMP-0022206-4: RES, 20.0, 1%, 0.1 W, AEC-Q200 Grade 0, 0603; Manufacturer: Vishay-Dale; Value: 20.0; Res_ohm: 20; Value_Code: 20R0; Power_W: 100mW; Value2: 0.1W; VDC_V: 75V; TempCo: 100 ppm/C; EIA_Code: E96; AEC Category: Q200; AEC Qualified: Y; AEC Grade: 0; SizeX_mm: 1.6; SizeY_mm: 0.8; SizeZ_mm: 1; SizeArea_mm2: 1.28
R86 = CMP-0023191-5: RES, 57.6 k, 1%, 0.1 W, 0603; Manufacturer: Yageo; Power_W: 100mW; TempCo: 100 ppm/C; Value_Code: 57k6; Value: 57.6k; EIA_Code: E96; SizeX_mm: 1.6; SizeY_mm: 0.8; SizeZ_mm: 1; Value2: 0.1W; SizeArea_mm2: 1.28; AEC Qualified: N; VDC_V: 75V; AEC Category: Q200; SizeAreaWB_mm2: 4.68
R88 = CMP-0022735-5: RES, 100 k, 1%, 0.1 W, 0603; Manufacturer: Yageo; Power_W: 100mW; TempCo: 100 ppm/C; Value: 100k; EIA_Code: E96; SizeX_mm: 1.6; SizeY_mm: 0.8; SizeZ_mm: 1; Value2: 0.1W; SizeArea_mm2: 1.28; AEC Qualified: N; VDC_V: 75V; AEC Category: Q200; SizeAreaWB_mm2: 4.68
R91 = CMP-0023050-5: RES, 35.7 k, 1%, 0.1 W, 0603; Manufacturer: Yageo; Power_W: 100mW; TempCo: 100 ppm/C; Value_Code: 35k7; Value: 35.7k; EIA_Code: E96; SizeX_mm: 1.6; SizeY_mm: 0.8; SizeZ_mm: 1; Value2: 0.1W; SizeArea_mm2: 1.28; AEC Qualified: N; VDC_V: 75V; AEC Category: Q200; SizeAreaWB_mm2: 4.68
R92 = CMP-0023146-5: RES, 4.22 k, 1%, 0.1 W, 0603; Manufacturer: Yageo; Power_W: 100mW; TempCo: 100 ppm/C; Value_Code: 4k22; Value: 4.22k; EIA_Code: E96; SizeX_mm: 1.6; SizeY_mm: 0.8; SizeZ_mm: 1; Value2: 0.1W; SizeArea_mm2: 1.28; AEC Qualified: N; VDC_V: 75V; AEC Category: Q200; SizeAreaWB_mm2: 4.68
TP6 TP12 = CMP-0055160-2: Test Point, Multipurpose, Purple, TH; Manufacturer: Keystone Electronics; CNHeader: FALSE; CT: TRUE; ContactFinish: Silver
TP7-TP9 TP11 = CMP-0055147-2: Test Point, Multipurpose, Red, TH; Manufacturer: Keystone Electronics; CNHeader: FALSE; Green_Lifecycle: Active; Green_REACh: Passed; ContactFinish: Silver; CT: TRUE
TP10 = CMP-0055150-2: Test Point, Multipurpose, Orange, TH; Manufacturer: Keystone Electronics; CNHeader: FALSE; Green_Lifecycle: Active; Green_REACh: Passed; ContactFinish: Silver; CT: TRUE
TP13 TP14 = CMP-0003907-1: PIGTAIL; Manufacturer: Texas Instruments; CompType: Test Point
TP16-TP18 = CMP-0055148-2: Test Point, Multipurpose, Black, TH; Manufacturer: Keystone Electronics; CNHeader: FALSE; Green_Lifecycle: Active; Green_REACh: Passed; ContactFinish: Silver; CT: TRUE
U5 = CMP-0081563-2: Voltage Output, Unidirectional Measurement Current-Shunt Monitor, HKX0008A (CFP-8); Manufacturer: Texas Instruments; SizeZ_mm: 2.8; Rating: Space; AEC Category: Q200; CompType: IC; AEC Qualified: N
U6 = CMP-0121940-3: 200-V, 12-A eGaN Half Bridge Power Stage with Integrated Driver; Manufacturer: Texas Instruments; SizeZ_mm: 1.05mm; AEC Qualified: No; Max Supply Voltage: 16V; Min Supply Voltage: 10V; Number Of Outputs: 1; TJmax_C: +125°C; AEC Category: Q200; CompType: IC
U7 = CMP-0075734-1: High/Low Side, Bi-Directional Zero-Drift Current Sense Amp w/ Enhanced PWM Rejection, PW0008A (TSSOP-8); Manufacturer: Texas Instruments; CompType: IC; U/M: EA; SizeX_mm: 6.4; SizeAreaWB_mm2: 42.0; SizeZ_mm: 1.2; SizeY_mm: 3.0; SizeArea_mm2: 19.2

## Sheet TIDA-010984 Interface.SchDoc
size 431 x 279 mm; Date: Not shown in title block; ApprovedBy: Not shown in title block; CheckedBy: Not shown in title block; Author: Not shown in title block; CompanyName: Not shown in title block; Engineer: Not shown in title block; Organization: Not shown in title block; Address1: Not shown in title block; Address2: Not shown in title block; Address3: Not shown in title block; Address4: Not shown in title block; DocumentNumber: 2; Revision: Use project parameter SCH_Rev; SheetNumber: 2; SheetTotal: 6; PageSetup: Record=PageOptions¦CenterHorizontal=True¦CenterVertical=True¦PrintScale=1.00¦XCorrection=1.00¦YCorrection=1.00¦PrintKind=0¦BorderSize=5000000¦LeftOffset=0¦BottomOffset=0¦Orientation=2¦PaperLength=1000¦PaperWidth=1000¦Scale=100¦PaperSource=15¦PrintQuality=600¦MediaType=1¦DitherType=10¦PaperKind=Letter¦PrintScaleMode=1
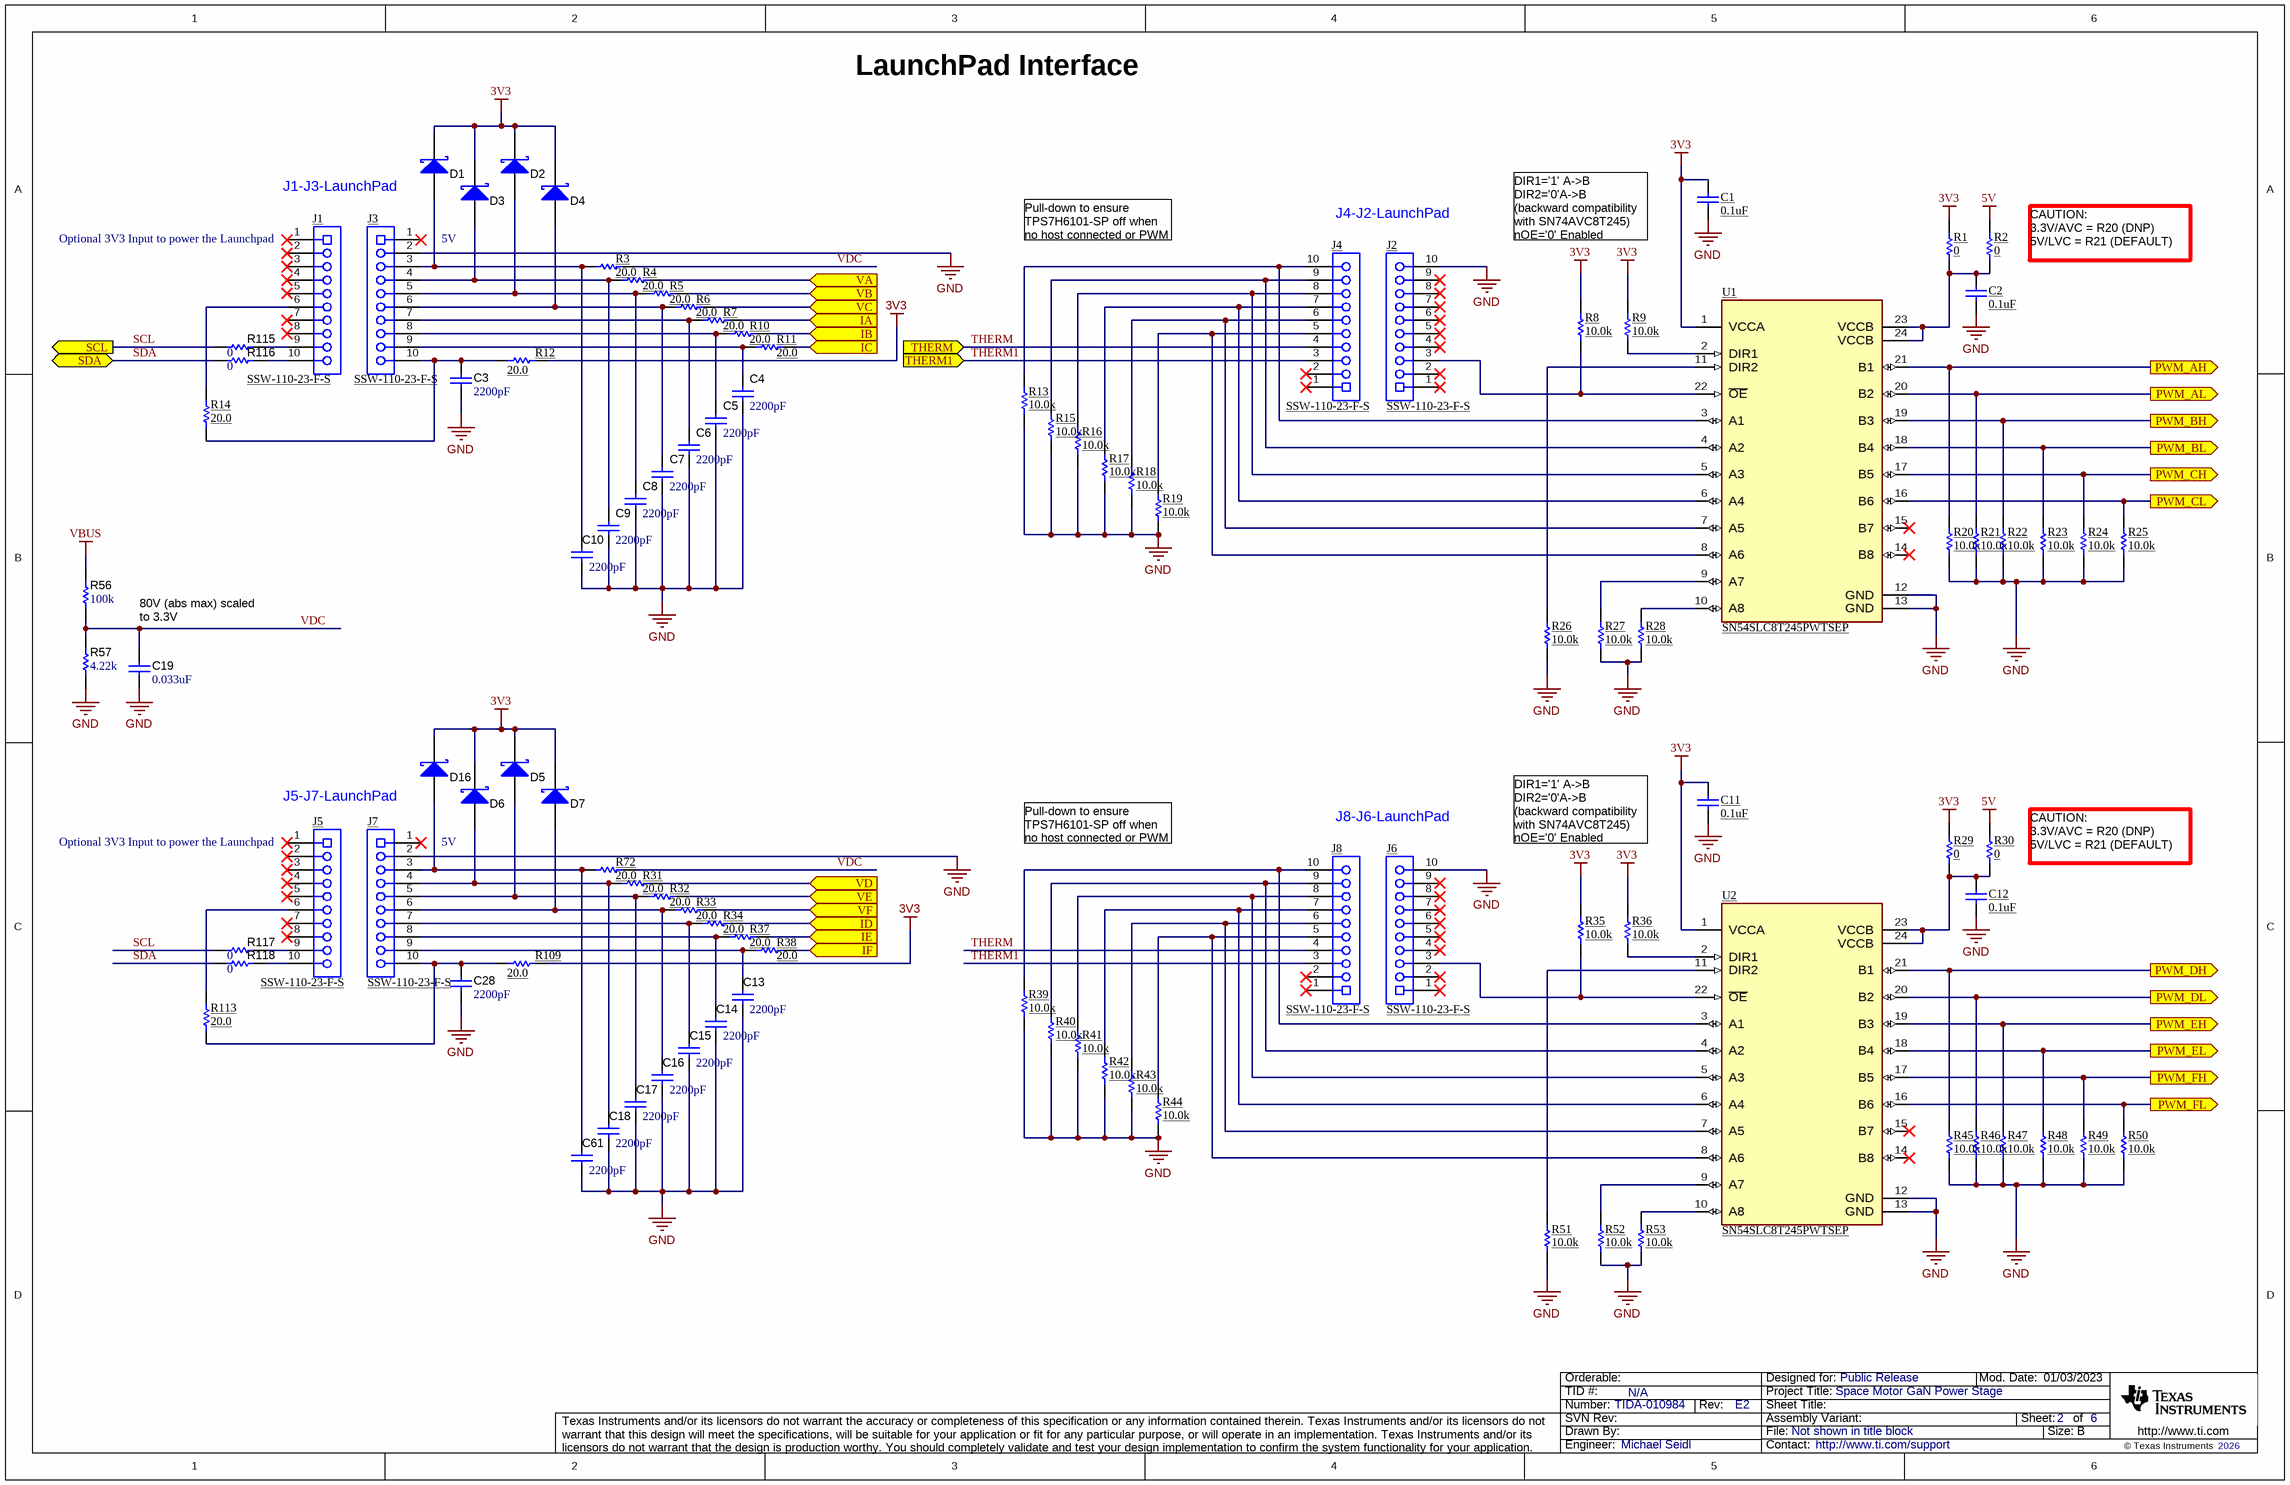
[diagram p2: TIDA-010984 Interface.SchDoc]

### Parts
C1  ValueDisplayed: 0.1uF  [0603]  (hidden comment: GRM188R71C104KA01D)
C2  ValueDisplayed: 0.1uF  [0603]  (hidden comment: GRM188R71C104KA01D)
C3  ValueDisplayed: 2200pF  [0603]  (hidden comment: CMP-0006827-4)
C4  ValueDisplayed: 2200pF  [0603]  (hidden comment: CMP-0006827-4)
C5  ValueDisplayed: 2200pF  [0603]  (hidden comment: CMP-0006827-4)
C6  ValueDisplayed: 2200pF  [0603]  (hidden comment: CMP-0006827-4)
C7  ValueDisplayed: 2200pF  [0603]  (hidden comment: CMP-0006827-4)
C8  ValueDisplayed: 2200pF  [0603]  (hidden comment: CMP-0006827-4)
C9  ValueDisplayed: 2200pF  [0603]  (hidden comment: CMP-0006827-4)
C10  ValueDisplayed: 2200pF  [0603]  (hidden comment: CMP-0006827-4)
C11  ValueDisplayed: 0.1uF  [0603]  (hidden comment: GRM188R71C104KA01D)
C12  ValueDisplayed: 0.1uF  [0603]  (hidden comment: GRM188R71C104KA01D)
C13  ValueDisplayed: 2200pF  [0603]  (hidden comment: CMP-0006827-4)
C14  ValueDisplayed: 2200pF  [0603]  (hidden comment: CMP-0006827-4)
C15  ValueDisplayed: 2200pF  [0603]  (hidden comment: CMP-0006827-4)
C16  ValueDisplayed: 2200pF  [0603]  (hidden comment: CMP-0006827-4)
C17  ValueDisplayed: 2200pF  [0603]  (hidden comment: CMP-0006827-4)
C18  ValueDisplayed: 2200pF  [0603]  (hidden comment: CMP-0006827-4)
C19  ValueDisplayed: 0.033uF  [0603]  (hidden comment: GRM188R71C333KA01D)
C28  ValueDisplayed: 2200pF  [0603]  (hidden comment: CMP-0006827-4)
C61  ValueDisplayed: 2200pF  [0603]  (hidden comment: CMP-0006827-4)
D1  1PS79SB70,115  [SOD-523]  (value not drawn)
D2  1PS79SB70,115  [SOD-523]  (value not drawn)
D3  1PS79SB70,115  [SOD-523]  (value not drawn)
D4  1PS79SB70,115  [SOD-523]  (value not drawn)
D5  1PS79SB70,115  [SOD-523]  (value not drawn)
D6  1PS79SB70,115  [SOD-523]  (value not drawn)
D7  1PS79SB70,115  [SOD-523]  (value not drawn)
D16  1PS79SB70,115  [SOD-523]  (value not drawn)
J1  SSW-110-23-F-S  [CONN_SSW-110-23-F-S]
J2  SSW-110-23-F-S  [CONN_SSW-110-23-F-S]
J3  SSW-110-23-F-S  [CONN_SSW-110-23-F-S]
J4  SSW-110-23-F-S  [CONN_SSW-110-23-F-S]
J5  SSW-110-23-F-S  [CONN_SSW-110-23-F-S]
J6  SSW-110-23-F-S  [CONN_SSW-110-23-F-S]
J7  SSW-110-23-F-S  [CONN_SSW-110-23-F-S]
J8  SSW-110-23-F-S  [CONN_SSW-110-23-F-S]
R1  ValueDisplayed: 0  [0603]  (hidden comment: RC0603JR-070RL)
R2  ValueDisplayed: 0  [0603]  (hidden comment: RC0603JR-070RL)
R3  ValueDisplayed: 20.0  [0603]  (hidden comment: RC0603FR-0720RL)
R4  ValueDisplayed: 20.0  [0603]  (hidden comment: RC0603FR-0720RL)
R5  ValueDisplayed: 20.0  [0603]  (hidden comment: RC0603FR-0720RL)
R6  ValueDisplayed: 20.0  [0603]  (hidden comment: RC0603FR-0720RL)
R7  ValueDisplayed: 20.0  [0603]  (hidden comment: RC0603FR-0720RL)
R8  ValueDisplayed: 10.0k  [0603]  (hidden comment: RC0603FR-0710KL)
R9  ValueDisplayed: 10.0k  [0603]  (hidden comment: RC0603FR-0710KL)
R10  ValueDisplayed: 20.0  [0603]  (hidden comment: RC0603FR-0720RL)
R11  ValueDisplayed: 20.0  [0603]  (hidden comment: RC0603FR-0720RL)
R12  ValueDisplayed: 20.0  [0603]  (hidden comment: RC0603FR-0720RL)
R13  ValueDisplayed: 10.0k  [0603]  (hidden comment: RC0603FR-0710KL)
R14  ValueDisplayed: 20.0  [0603]  (hidden comment: RC0603FR-0720RL)
R15  ValueDisplayed: 10.0k  [0603]  (hidden comment: RC0603FR-0710KL)
R16  ValueDisplayed: 10.0k  [0603]  (hidden comment: RC0603FR-0710KL)
R17  ValueDisplayed: 10.0k  [0603]  (hidden comment: RC0603FR-0710KL)
R18  ValueDisplayed: 10.0k  [0603]  (hidden comment: RC0603FR-0710KL)
R19  ValueDisplayed: 10.0k  [0603]  (hidden comment: RC0603FR-0710KL)
R20  ValueDisplayed: 10.0k  [0603]  (hidden comment: RC0603FR-0710KL)
R21  ValueDisplayed: 10.0k  [0603]  (hidden comment: RC0603FR-0710KL)
R22  ValueDisplayed: 10.0k  [0603]  (hidden comment: RC0603FR-0710KL)
R23  ValueDisplayed: 10.0k  [0603]  (hidden comment: RC0603FR-0710KL)
R24  ValueDisplayed: 10.0k  [0603]  (hidden comment: RC0603FR-0710KL)
R25  ValueDisplayed: 10.0k  [0603]  (hidden comment: RC0603FR-0710KL)
R26  ValueDisplayed: 10.0k  [0603]  (hidden comment: RC0603FR-0710KL)
R27  ValueDisplayed: 10.0k  [0603]  (hidden comment: RC0603FR-0710KL)
R28  ValueDisplayed: 10.0k  [0603]  (hidden comment: RC0603FR-0710KL)
R29  ValueDisplayed: 0  [0603]  (hidden comment: RC0603JR-070RL)
R30  ValueDisplayed: 0  [0603]  (hidden comment: RC0603JR-070RL)
R31  ValueDisplayed: 20.0  [0603]  (hidden comment: RC0603FR-0720RL)
R32  ValueDisplayed: 20.0  [0603]  (hidden comment: RC0603FR-0720RL)
R33  ValueDisplayed: 20.0  [0603]  (hidden comment: RC0603FR-0720RL)
R34  ValueDisplayed: 20.0  [0603]  (hidden comment: RC0603FR-0720RL)
R35  ValueDisplayed: 10.0k  [0603]  (hidden comment: RC0603FR-0710KL)
R36  ValueDisplayed: 10.0k  [0603]  (hidden comment: RC0603FR-0710KL)
R37  ValueDisplayed: 20.0  [0603]  (hidden comment: RC0603FR-0720RL)
R38  ValueDisplayed: 20.0  [0603]  (hidden comment: RC0603FR-0720RL)
R39  ValueDisplayed: 10.0k  [0603]  (hidden comment: RC0603FR-0710KL)
R40  ValueDisplayed: 10.0k  [0603]  (hidden comment: RC0603FR-0710KL)
R41  ValueDisplayed: 10.0k  [0603]  (hidden comment: RC0603FR-0710KL)
R42  ValueDisplayed: 10.0k  [0603]  (hidden comment: RC0603FR-0710KL)
R43  ValueDisplayed: 10.0k  [0603]  (hidden comment: RC0603FR-0710KL)
R44  ValueDisplayed: 10.0k  [0603]  (hidden comment: RC0603FR-0710KL)
R45  ValueDisplayed: 10.0k  [0603]  (hidden comment: RC0603FR-0710KL)
R46  ValueDisplayed: 10.0k  [0603]  (hidden comment: RC0603FR-0710KL)
R47  ValueDisplayed: 10.0k  [0603]  (hidden comment: RC0603FR-0710KL)
R48  ValueDisplayed: 10.0k  [0603]  (hidden comment: RC0603FR-0710KL)
R49  ValueDisplayed: 10.0k  [0603]  (hidden comment: RC0603FR-0710KL)
R50  ValueDisplayed: 10.0k  [0603]  (hidden comment: RC0603FR-0710KL)
R51  ValueDisplayed: 10.0k  [0603]  (hidden comment: RC0603FR-0710KL)
R52  ValueDisplayed: 10.0k  [0603]  (hidden comment: RC0603FR-0710KL)
R53  ValueDisplayed: 10.0k  [0603]  (hidden comment: RC0603FR-0710KL)
R56  ValueDisplayed: 100k  [0603]  (hidden comment: RC0603FR-07100KL)
R57  ValueDisplayed: 4.22k  [0603]  (hidden comment: RC0603FR-074K22L)
R72  ValueDisplayed: 20.0  [0603]  (hidden comment: RC0603FR-0720RL)
R109  ValueDisplayed: 20.0  [0603]  (hidden comment: RC0603FR-0720RL)
R113  ValueDisplayed: 20.0  [0603]  (hidden comment: RC0603FR-0720RL)
R115  ValueDisplayed: 0  [0603]  (hidden comment: RC0603JR-070RL)
R116  ValueDisplayed: 0  [0603]  (hidden comment: RC0603JR-070RL)
R117  ValueDisplayed: 0  [0603]  (hidden comment: RC0603JR-070RL)
R118  ValueDisplayed: 0  [0603]  (hidden comment: RC0603JR-070RL)
U1  SN54SLC8T245PWTSEP  [PW0024A-MFG]
U2  SN54SLC8T245PWTSEP  [PW0024A-MFG]

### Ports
IA (in), IB (in), IC (in), ID (in), IE (in), IF (in), PWM_AH (out), PWM_AL (out), PWM_BH (out), PWM_BL (out), PWM_CH (out), PWM_CL (out), PWM_DH (out), PWM_DL (out), PWM_EH (out), PWM_EL (out), PWM_FH (out), PWM_FL (out), SCL (out), SDA (bidir), THERM1 (in), THERM (in), VA (in), VB (in), VC (in), VD (in), VE (in), VF (in)

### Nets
3V3: C1.1 C11.1 D1.1(K) D2.1(K) D3.1(K) D4.1(K) D5.1(K) D6.1(K) D7.1(K) D16.1(K) R1.1 R8.2 R9.2 R12.1 R29.1 R35.2 R36.2 R109.1 U1.1(VCCA) U2.1(VCCA)
5V: R2.1 R30.1
GND: C1.2 C2.2 C3.2 C4.2 C5.2 C6.2 C7.2 C8.2 C9.2 C10.2 C11.2 C12.2 C13.2 C14.2 C15.2 C16.2 C17.2 C18.2 C19.2 C28.2 C61.2 J2.10 J3.2 J6.10 J7.2 R13.1 R15.1 R16.1 R17.1 R18.1 R19.1 R20.1 R21.1 R22.1 R23.1 R24.1 R25.1 R26.1 R27.1 R28.1 R39.1 R40.1 R41.1 R42.1 R43.1 R44.1 R45.1 R46.1 R47.1 R48.1 R49.1 R50.1 R51.1 R52.1 R53.1 R57.1 U1.12(GND) U1.13(GND) U2.12(GND) U2.13(GND)
VBUS: R56.2
CS: R7.1 ; port IA
CS: R10.1 ; port IB  [a separate net that carries the same name]
CS: R11.1 ; port IC  [a separate net that carries the same name]
CS: R37.1 ; port IE  [a separate net that carries the same name]
CS: R34.1 ; port ID  [a separate net that carries the same name]
CS: R38.1 ; port IF  [a separate net that carries the same name]
PWM_AH: R20.2 U1.21(B1) ; port PWM_AH
PWM_AL: R21.2 U1.20(B2) ; port PWM_AL
PWM_BH: R22.2 U1.19(B3) ; port PWM_BH
PWM_BL: R23.2 U1.18(B4) ; port PWM_BL
PWM_CH: R24.2 U1.17(B5) ; port PWM_CH
PWM_CL: R25.2 U1.16(B6) ; port PWM_CL
PWM_DH: R45.2 U2.21(B1) ; port PWM_DH
PWM_DL: R46.2 U2.20(B2) ; port PWM_DL
PWM_EH: R47.2 U2.19(B3) ; port PWM_EH
PWM_EL: R48.2 U2.18(B4) ; port PWM_EL
PWM_FH: R49.2 U2.17(B5) ; port PWM_FH
PWM_FL: R50.2 U2.16(B6) ; port PWM_FL
SCL: R115.1 R117.1 ; port SCL
SDA: R116.1 R118.1 ; port SDA
THERM: J4.4 J8.4 ; port THERM
THERM1: J4.3 J8.3 ; port THERM1
V_PH: R4.1 ; port VA
V_PH: R5.1 ; port VB  [a separate net that carries the same name]
V_PH: R6.1 ; port VC  [a separate net that carries the same name]
V_PH: R32.1 ; port VE  [a separate net that carries the same name]
V_PH: R31.1 ; port VD  [a separate net that carries the same name]
V_PH: R33.1 ; port VF  [a separate net that carries the same name]
VDC: C19.1 R3.1 R56.1 R57.2 R72.1
NetC2_1: C2.1 R1.2 R2.2 U1.23(VCCB) U1.24(VCCB)
NetC3_1: C3.1 J3.10 R12.2 R14.1
NetC4_1: C4.1 J3.9 R11.2
NetC5_1: C5.1 J3.8 R10.2
NetC6_1: C6.1 J3.7 R7.2
NetC7_1: C7.1 D4.2(A) J3.6 R6.2
NetC8_1: C8.1 D2.2(A) J3.5 R5.2
NetC9_1: C9.1 D3.2(A) J3.4 R4.2
NetC10_1: C10.1 D1.2(A) J3.3 R3.2
NetC12_1: C12.1 R29.2 R30.2 U2.23(VCCB) U2.24(VCCB)
NetC13_1: C13.1 J7.9 R38.2
NetC14_1: C14.1 J7.8 R37.2
NetC15_1: C15.1 J7.7 R34.2
NetC16_1: C16.1 D7.2(A) J7.6 R33.2
NetC17_1: C17.1 D5.2(A) J7.5 R32.2
NetC18_1: C18.1 D6.2(A) J7.4 R31.2
NetC28_1: C28.1 J7.10 R109.2 R113.1
NetC61_1: C61.1 D16.2(A) J7.3 R72.2
NetJ1_6: J1.6 R14.2
NetJ1_9: J1.9 R115.2
NetJ1_10: J1.10 R116.2
NetJ2_3: J2.3 R8.1 U1.22(~{OE})
NetJ4_5: J4.5 R19.2 U1.8(A6)
NetJ4_6: J4.6 R18.2 U1.7(A5)
NetJ4_7: J4.7 R17.2 U1.6(A4)
NetJ4_8: J4.8 R16.2 U1.5(A3)
NetJ4_9: J4.9 R15.2 U1.4(A2)
NetJ4_10: J4.10 R13.2 U1.3(A1)
NetJ5_6: J5.6 R113.2
NetJ5_9: J5.9 R117.2
NetJ5_10: J5.10 R118.2
NetJ6_3: J6.3 R35.1 U2.22(~{OE})
NetJ8_5: J8.5 R44.2 U2.8(A6)
NetJ8_6: J8.6 R43.2 U2.7(A5)
NetJ8_7: J8.7 R42.2 U2.6(A4)
NetJ8_8: J8.8 R41.2 U2.5(A3)
NetJ8_9: J8.9 R40.2 U2.4(A2)
NetJ8_10: J8.10 R39.2 U2.3(A1)
NetR9_1: R9.1 U1.2(DIR1)
NetR26_2: R26.2 U1.11(DIR2)
NetR27_2: R27.2 U1.9(A7)
NetR28_2: R28.2 U1.10(A8)
NetR36_1: R36.1 U2.2(DIR1)
NetR51_2: R51.2 U2.11(DIR2)
NetR52_2: R52.2 U2.9(A7)
NetR53_2: R53.2 U2.10(A8)

Not connected (* = marked no-connect by the designer): J1 1* 2* 3* 4* 5* 7* 8*; J2 1* 2* 4* 5* 6* 7* 8* 9*; J3 1*; J4 1* 2*; J5 1* 2* 3* 4* 5* 7* 8*; J6 1* 2* 4* 5* 6* 7* 8* 9*; J7 1*; J8 1* 2*; U1 14(B8)* 15(B7)*; U2 14(B8)* 15(B7)*

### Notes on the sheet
- LaunchPad Interface
- J1-J3-LaunchPad
- J4-J2-LaunchPad
- (near J1) Optional 3V3 Input to power the Launchpad
- 5V
- Pull-down to ensure TPS7H6101-SP off when no host connected or PWM HIZ
- DIR1='1' A->B
  DIR2='0'A->B
  (backward compatibility
  with SN74AVC8T245)
  nOE='0' Enabled
- CAUTION:
  3.3V/AVC = R20 (DNP)
  5V/LVC = R21 (DEFAULT)
- 80V (abs max) scaled to 3.3V
- J5-J7-LaunchPad
- J8-J6-LaunchPad
- (near J5) Optional 3V3 Input to power the Launchpad

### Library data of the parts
C1 C2 C11 C12 = CMP-0007378-5: CAP, CERM, 0.1 uF, 16 V, +/- 10%, X7R, 0603; Manufacturer: MuRata; Polarized: N; Value: 0.1uF; U/M: EA; Cap_F: 100nF; Value1: Unknown; VDC_V: 16V; TaMin_C: -55°C; TaMax_C: 125°C; SizeArea_mm2: 1.28; SizeAreaWB_mm2: 4.68; SizeX_mm: 1.6; SizeY_mm: 0.8; SizeZ_mm: 1; AEC Category: Q200
C3-C10 C13-C18 C28 C61 = CMP-0006827-4: CAP, CERM, 2200 pF, 16 V, +/- 10%, X7R, 0603; PartNumber: 885012206036; Manufacturer: Wurth Elektronik; Polarized: N; Value: 2200pF; U/M: EA; Cap_F: 2.2nF; Value1: Unknown; VDC_V: 16V; TaMin_C: -55°C; TaMax_C: 125°C; AEC Category: Q200; SizeArea_mm2: 1.28; SizeAreaWB_mm2: 4.68; SizeX_mm: 1.6; SizeY_mm: 0.8; SizeZ_mm: 1
C19 = CMP-0007392-5: as C53 on sheet TIDA-010984 PowerStage
D1-D7 D16 = CMP-0028644-3: Diode, Schottky, 70 V, 0.07 A, SOD-523; Manufacturer: Nexperia; Vf_V: 410mV; Value: 70V; Value1: 0.07A; Value2: 0.41V; Io_A: 70mA; TJmax_C: 150°C; SizeAreaWB_mm2: 5.13; SizeArea_mm2: 1.53; SizeX_mm: 1.7; SizeY_mm: 0.9; SizeZ_mm: 0.65; AEC Category: Q101; Green_Lifecycle: Not Set; Green_REACh: Incomplete
J1-J8 = CMP-0075441-1: Connector, Receptacle, 100mil, 10x1, Gold plated, TH; Manufacturer: Samtec; Green_Lifecycle: Active; CompType: Socket Strip; Green_REACh: Passed; CT: True; CNHeader: False
R1 R2 R29 R30 R115-R118 = CMP-0025885-5: as R75 on sheet TIDA-010984 PowerStage
R3-R7 R10-R12 R14 R31-R34 R37 R38 R72 R109 R113 = CMP-0022908-4: RES, 20.0, 1%, 0.1 W, 0603; Manufacturer: Yageo; Power_W: 100mW; TempCo: 100 ppm/C; Value_Code: 20R0; Value: 20.0; EIA_Code: E96; Res_ohm: 20; SizeX_mm: 1.6; SizeY_mm: 0.8; SizeZ_mm: 1; Value2: 0.1W; SizeArea_mm2: 1.28; AEC Qualified: N; VDC_V: 75V; AEC Category: Q200; SizeAreaWB_mm2: 4.68
R8 R9 R13 R15-R28 R35 R36 R39-R53 = CMP-0022746-5: as R81 on sheet TIDA-010984 PowerStage
R56 = CMP-0022735-5: as R88 on sheet TIDA-010984 PowerStage
R57 = CMP-0023146-5: RES, 4.22 k, 1%, 0.1 W, 0603; Manufacturer: Yageo; Value: 4.22k; Value_Code: 4k22; Power_W: 100mW; Value2: 0.1W; VDC_V: 75V; TempCo: 100 ppm/C; EIA_Code: E96; AEC Category: Q200; AEC Qualified: N; SizeArea_mm2: 1.28; SizeX_mm: 1.6; SizeY_mm: 0.8; SizeZ_mm: 1; SizeAreaWB_mm2: 4.68
U1 U2 = CMP-0122972-1: 8-Bit Dual-Supply Bus Transceiver With Configurable Voltage Translation and Tri-State Outputs; Manufacturer: Texas Instruments; SizeZ_mm: 1.2mm; AEC Qualified: No; Data Rate: 380Mbits/s; Logic Function Desc: Non-Inverting; Nominal Supply Current: 70uA; Number Of Inputs: 8; PositionCount: 1; Propagation Delay: 2ns; Standoff Height: 0.05mm; TaMax_C: +125°C; TaMin_C: -55°C; TJmax_C: +150°C; V A Max: 3.6V; V A Min: 0.65V

## Sheet TIDA-010984 Hardware.SchDoc
size 431 x 279 mm; Date: Not shown in title block; ApprovedBy: Not shown in title block; CheckedBy: Not shown in title block; Author: Not shown in title block; CompanyName: Not shown in title block; DrawnBy: Michael Seidl; Engineer: Not shown in title block; Organization: Not shown in title block; Address1: Not shown in title block; Address2: Not shown in title block; Address3: Not shown in title block; Address4: Not shown in title block; DocumentNumber: 3; Revision: Use project parameter SCH_Rev; SheetNumber: 6; SheetTotal: 6; PageSetup: Record=PageOptions¦CenterHorizontal=True¦CenterVertical=True¦PrintScale=1.00¦XCorrection=1.00¦YCorrection=1.00¦PrintKind=0¦BorderSize=5000000¦LeftOffset=0¦BottomOffset=0¦Orientation=2¦PaperLength=1000¦PaperWidth=1000¦Scale=100¦PaperSource=15¦PrintQuality=600¦MediaType=1¦DitherType=10¦PaperKind=Letter¦PrintScaleMode=1
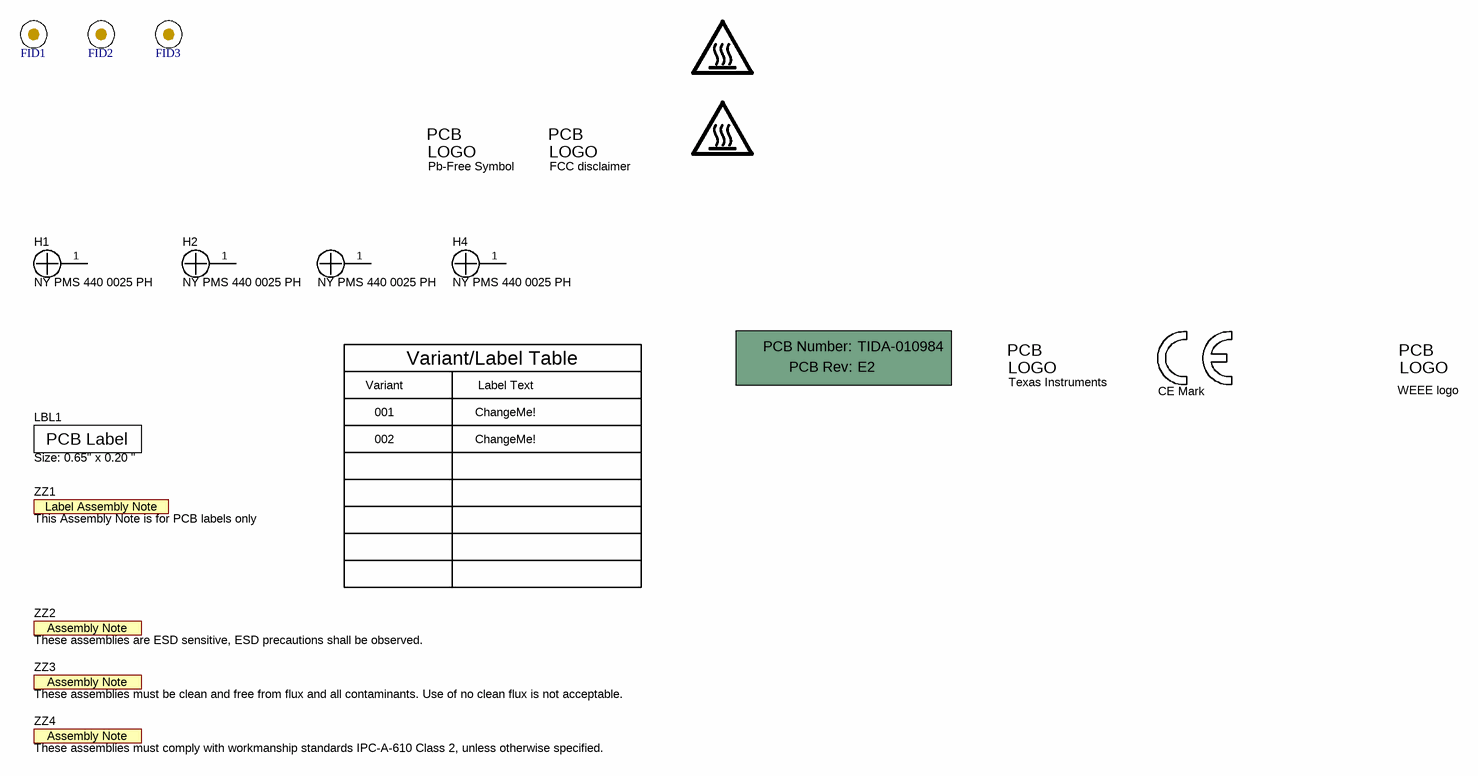
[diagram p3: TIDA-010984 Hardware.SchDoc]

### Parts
5  CAUTION HOT SURFACE  [IEC_HotSurface_Small]  (value not drawn)  (no BOM)
!PCB?  Printed Circuit Board  (value not drawn)  (mechanical)
FID1  Fiducial  [Fiducial10-20]  (value not drawn)
FID2  Fiducial  [Fiducial10-20]  (value not drawn)
FID3  Fiducial  [Fiducial10-20]  (value not drawn)
H1  NY PMS 440 0025 PH  [NY PMS 440 0025 PH]
H2  NY PMS 440 0025 PH  [NY PMS 440 0025 PH]
H3  NY PMS 440 0025 PH  [NY PMS 440 0025 PH]
H4  NY PMS 440 0025 PH  [NY PMS 440 0025 PH]
LBL1  Size: 0.65" x 0.20 "  [Label_650x200]
Logo1  Texas Instruments  [TI_Stacked_Overlay_Small]  (no BOM)
Logo2  CE Mark  [CE_Mark_5mm]  (no BOM)
Logo3  WEEE logo  [WEEE_Minimum]  (no BOM)
LOGO4  CAUTION HOT SURFACE  [IEC_HotSurface_Small]  (value not drawn)  (no BOM)
Logo6  FCC disclaimer  [FCC_disclaimer]  (no BOM)
Logo7  Pb-Free Symbol  [Pb-Free_Overlay_Small]  (no BOM)
ZZ1  This Assembly Note is for PCB labels only  [AssemblyNoteLabel]  (no BOM)
ZZ2  These assemblies are ESD sensitive, ESD precautions shall be observed.  [AssemblyNote]  (no BOM)
ZZ3  These assemblies must be clean and free from flux and all contaminants. Use of no clean flux is not acceptable.  [AssemblyNote]  (no BOM)
ZZ4  These assemblies must comply with workmanship standards IPC-A-610 Class 2, unless otherwise specified.  [AssemblyNote]  (no BOM)

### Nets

Not connected (* = marked no-connect by the designer): H1 1; H2 1; H3 1; H4 1

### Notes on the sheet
- Variant
- 001
- Variant/Label Table
- Label Text
- ChangeMe!
- 002

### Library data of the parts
5 LOGO4 = CMP-0074837-2: IEC 61010-1 Hot Surface Warning; Manufacturer: Texas Instruments; SymbolCreator: a0412235; AEC Category: Q200; CompType: IC
!PCB? = CMP-0003618-2: Manufacturer: Any; PartNumber: TIDA-010984
FID1-FID3 = CMP-0077181-1: Fiducial mark.  There is nothing to buy or mount.
H1-H4 = CMP-0003617-1: Machine Screw, Round, #4-40 x 1/4, Nylon, Philips panhead; Manufacturer: B&F Fastener Supply; CompType: Hardware
LBL1 = THT-14-423-10: Thermal Transfer Printable Labels, 0.650" W x 0.200" H - 10,000 per roll; Manufacturer: Brady; SymbolCreator: a0412235; CompType: Label
Logo1 = CMP-0074838-1: Texas Instrument Corporate Signature; SymbolCreator: a0412235; Lib Reference: TI_Logo; Library Reference: Logo
Logo2 = CMP-0074844-2: Manufacturer: Texas Instruments; SymbolCreator: a0412235; AEC Category: Q200; CompType: IC
Logo3 = CMP-0074769-4: Manufacturer: Texas Instruments; CompType: IC; AEC Category: Q200
Logo6 = CMP-0074847-1: FCC_disclaimer
Logo7 = CMP-0074839-1: SymbolCreator: a0412235
ZZ1 = CMP-0003616-3
ZZ2 = CMP-0077236-1
ZZ3 = CMP-0077237-1
ZZ4 = CMP-0077238-1

## Sheet TIDA-010984 TempSensing.SchDoc
size 431 x 279 mm; Date: Not shown in title block; ApprovedBy: Not shown in title block; CheckedBy: Not shown in title block; Author: Not shown in title block; CompanyName: Not shown in title block; Engineer: Not shown in title block; Organization: Not shown in title block; Address1: Not shown in title block; Address2: Not shown in title block; Address3: Not shown in title block; Address4: Not shown in title block; DocumentNumber: 2; Revision: Use project parameter SCH_Rev; SheetNumber: 5; SheetTotal: 6; PageSetup: Record=PageOptions¦CenterHorizontal=True¦CenterVertical=True¦PrintScale=1.00¦XCorrection=1.00¦YCorrection=1.00¦PrintKind=0¦BorderSize=5000000¦LeftOffset=0¦BottomOffset=0¦Orientation=2¦PaperLength=1000¦PaperWidth=1000¦Scale=100¦PaperSource=15¦PrintQuality=600¦MediaType=1¦DitherType=10¦PaperKind=Letter¦PrintScaleMode=1
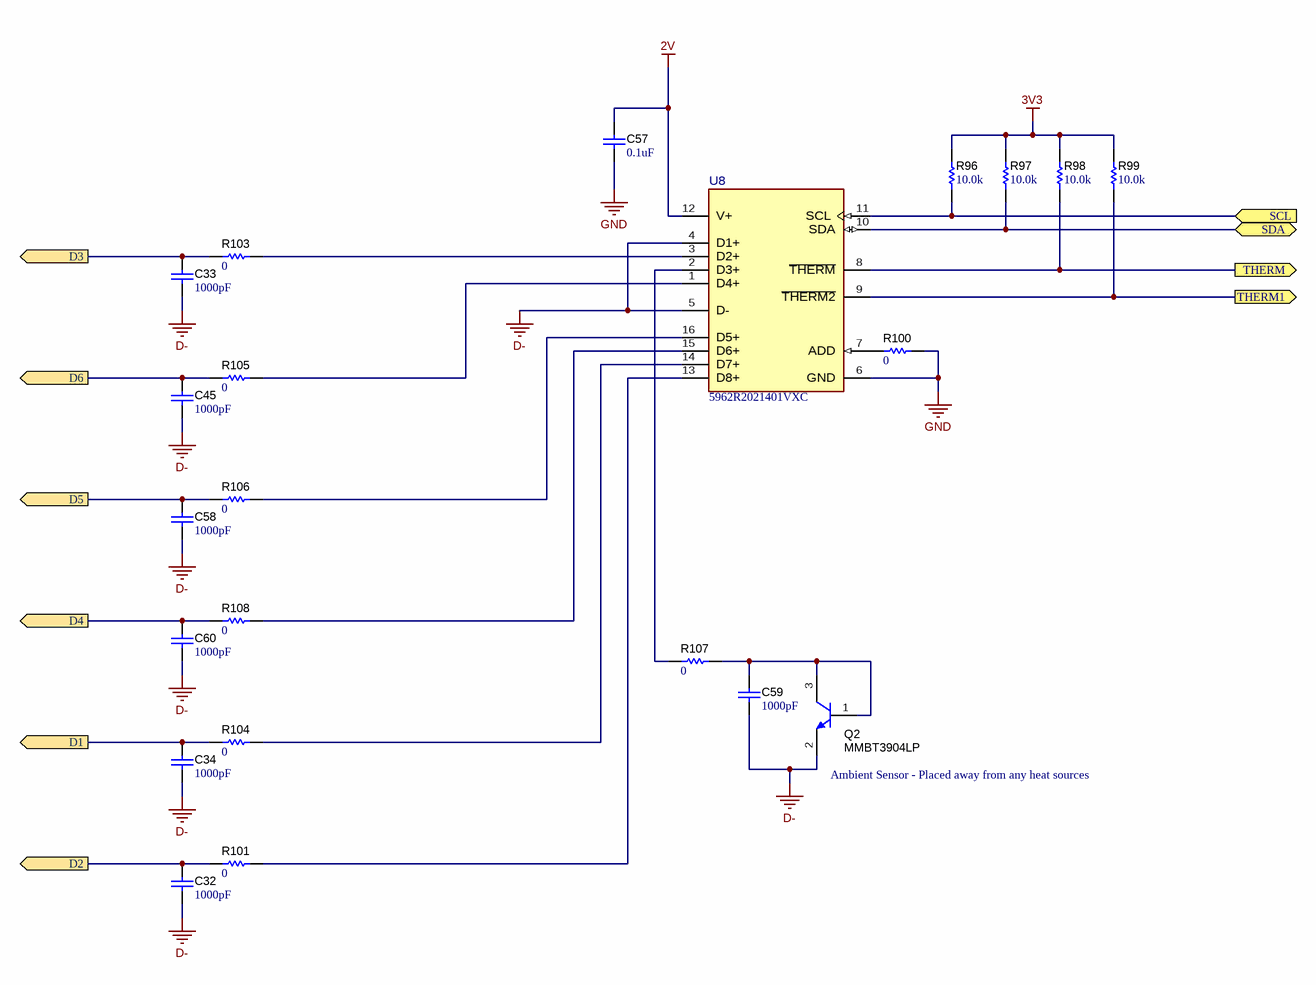
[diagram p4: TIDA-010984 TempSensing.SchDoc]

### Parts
C32  ValueDisplayed: 1000pF  [0603]  (hidden comment: 885012206034)
C33  ValueDisplayed: 1000pF  [0603]  (hidden comment: 885012206034)
C34  ValueDisplayed: 1000pF  [0603]  (hidden comment: 885012206034)
C45  ValueDisplayed: 1000pF  [0603]  (hidden comment: 885012206034)
C57  ValueDisplayed: 0.1uF  [0603]  (hidden comment: GRM188R71C104KA01D)
C58  ValueDisplayed: 1000pF  [0603]  (hidden comment: 885012206034)
C59  ValueDisplayed: 1000pF  [0603]  (hidden comment: 885012206034)
C60  ValueDisplayed: 1000pF  [0603]  (hidden comment: 885012206034)
Q2  MMBT3904LP  [DIODES_X1-DFN1006-3]
R96  ValueDisplayed: 10.0k  [0603]  (hidden comment: RC0603FR-0710KL)
R97  ValueDisplayed: 10.0k  [0603]  (hidden comment: RC0603FR-0710KL)
R98  ValueDisplayed: 10.0k  [0603]  (hidden comment: RC0603FR-0710KL)
R99  ValueDisplayed: 10.0k  [0603]  (hidden comment: RC0603FR-0710KL)
R100  ValueDisplayed: 0  [0603]  (hidden comment: RC0603JR-070RL)
R101  ValueDisplayed: 0  [0603]  (hidden comment: RC0603JR-070RL)
R103  ValueDisplayed: 0  [0603]  (hidden comment: RC0603JR-070RL)
R104  ValueDisplayed: 0  [0603]  (hidden comment: RC0603JR-070RL)
R105  ValueDisplayed: 0  [0603]  (hidden comment: RC0603JR-070RL)
R106  ValueDisplayed: 0  [0603]  (hidden comment: RC0603JR-070RL)
R107  ValueDisplayed: 0  [0603]  (hidden comment: RC0603JR-070RL)
R108  ValueDisplayed: 0  [0603]  (hidden comment: RC0603JR-070RL)
U8  5962R2021401VXC  [HKT0016A-IPC_C]

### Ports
D1 (out), D2 (out), D3 (out), D4 (out), D5 (out), D6 (out), SCL (in), SDA (bidir), THERM1 (out), THERM (out)

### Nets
2V: C57.2 U8.12(V+)
3V3: R96.2 R97.2 R98.2 R99.2
D-: C32.1 C33.1 C34.1 C45.1 C58.1 C59.1 C60.1 Q2.2(E) U8.4(D1+) U8.5(D-)
GND: C57.1 R100.2 U8.6(GND)
D+: C34.2 R104.1 ; port D1
D+: C32.2 R101.1 ; port D2  [a separate net that carries the same name]
D+: C33.2 R103.1 ; port D3  [a separate net that carries the same name]
D+: C58.2 R106.1 ; port D5  [a separate net that carries the same name]
D+: C60.2 R108.1 ; port D4  [a separate net that carries the same name]
D+: C45.2 R105.1 ; port D6  [a separate net that carries the same name]
SCL: R96.1 U8.11(SCL) ; port SCL
SDA: R97.1 U8.10(SDA) ; port SDA
THERM: R98.1 U8.8(~{THERM}) ; port THERM
THERM1: R99.1 U8.9(~{THERM2}) ; port THERM1
NetC59_2: C59.2 Q2.1(B) Q2.3(C) R107.2
NetR100_1: R100.1 U8.7(ADD)
NetR101_2: R101.2 U8.13(D8+)
NetR103_2: R103.2 U8.3(D2+)
NetR104_2: R104.2 U8.14(D7+)
NetR105_2: R105.2 U8.1(D4+)
NetR106_2: R106.2 U8.16(D5+)
NetR107_1: R107.1 U8.2(D3+)
NetR108_2: R108.2 U8.15(D6+)

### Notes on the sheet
- (near Q2) Ambient Sensor - Placed away from any heat sources

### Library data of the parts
C32-C34 C45 C58-C60 = CMP-0006826-4: CAP, CERM, 1000 pF, 16 V, +/- 10%, X7R, 0603; Manufacturer: Wurth Elektronik; Polarized: N; Value: 1000pF; U/M: EA; Cap_F: 1nF; Value1: Unknown; VDC_V: 16V; TaMin_C: -55°C; TaMax_C: 125°C; SizeAreaWB_mm2: 4.68; SizeZ_mm: 1; SizeX_mm: 1.6; SizeY_mm: 0.8; SizeArea_mm2: 1.28; AEC Category: Q200
C57 = CMP-0007378-5: as C50 on sheet TIDA-010984 PowerStage
Q2 = CMP-0000409-2: as Q1 on sheet TIDA-010984 PowerStage
R96-R99 = CMP-0022746-5: as R81 on sheet TIDA-010984 PowerStage
R100 R101 R103-R108 = CMP-0025885-5: as R75 on sheet TIDA-010984 PowerStage
U8 = CMP-0097071-1: 9-Channel (8-Remote and 1-Local), High-Accuracy Temperature Sensor; Manufacturer: Texas Instruments; Standoff Height: 0.097mm; AEC Qualified: No; Sensor Output: I2C,SMBus; Min Supply Voltage: 1.7V; Accuracy: 2%; TaMax_C: +125°C; Interface: I2C,2-Wire,SMBus; TaMin_C: -55°C; SizeZ_mm: 2.227mm; Max Supply Voltage: 3.6V; TJmax_C: +150°C; Resolution: 13bits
